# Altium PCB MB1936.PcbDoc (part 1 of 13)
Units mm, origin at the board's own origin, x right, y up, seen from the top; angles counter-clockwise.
Board outline 172 x 137 mm, 6 copper layers (Top Layer, Signal Layer 1, Signal Layer 2, Signal Layer 3, Signal Layer 4, Bottom Layer), stack 1.549 mm thick; 859 components, 672 nets, 3477 pads, 2222 vias.
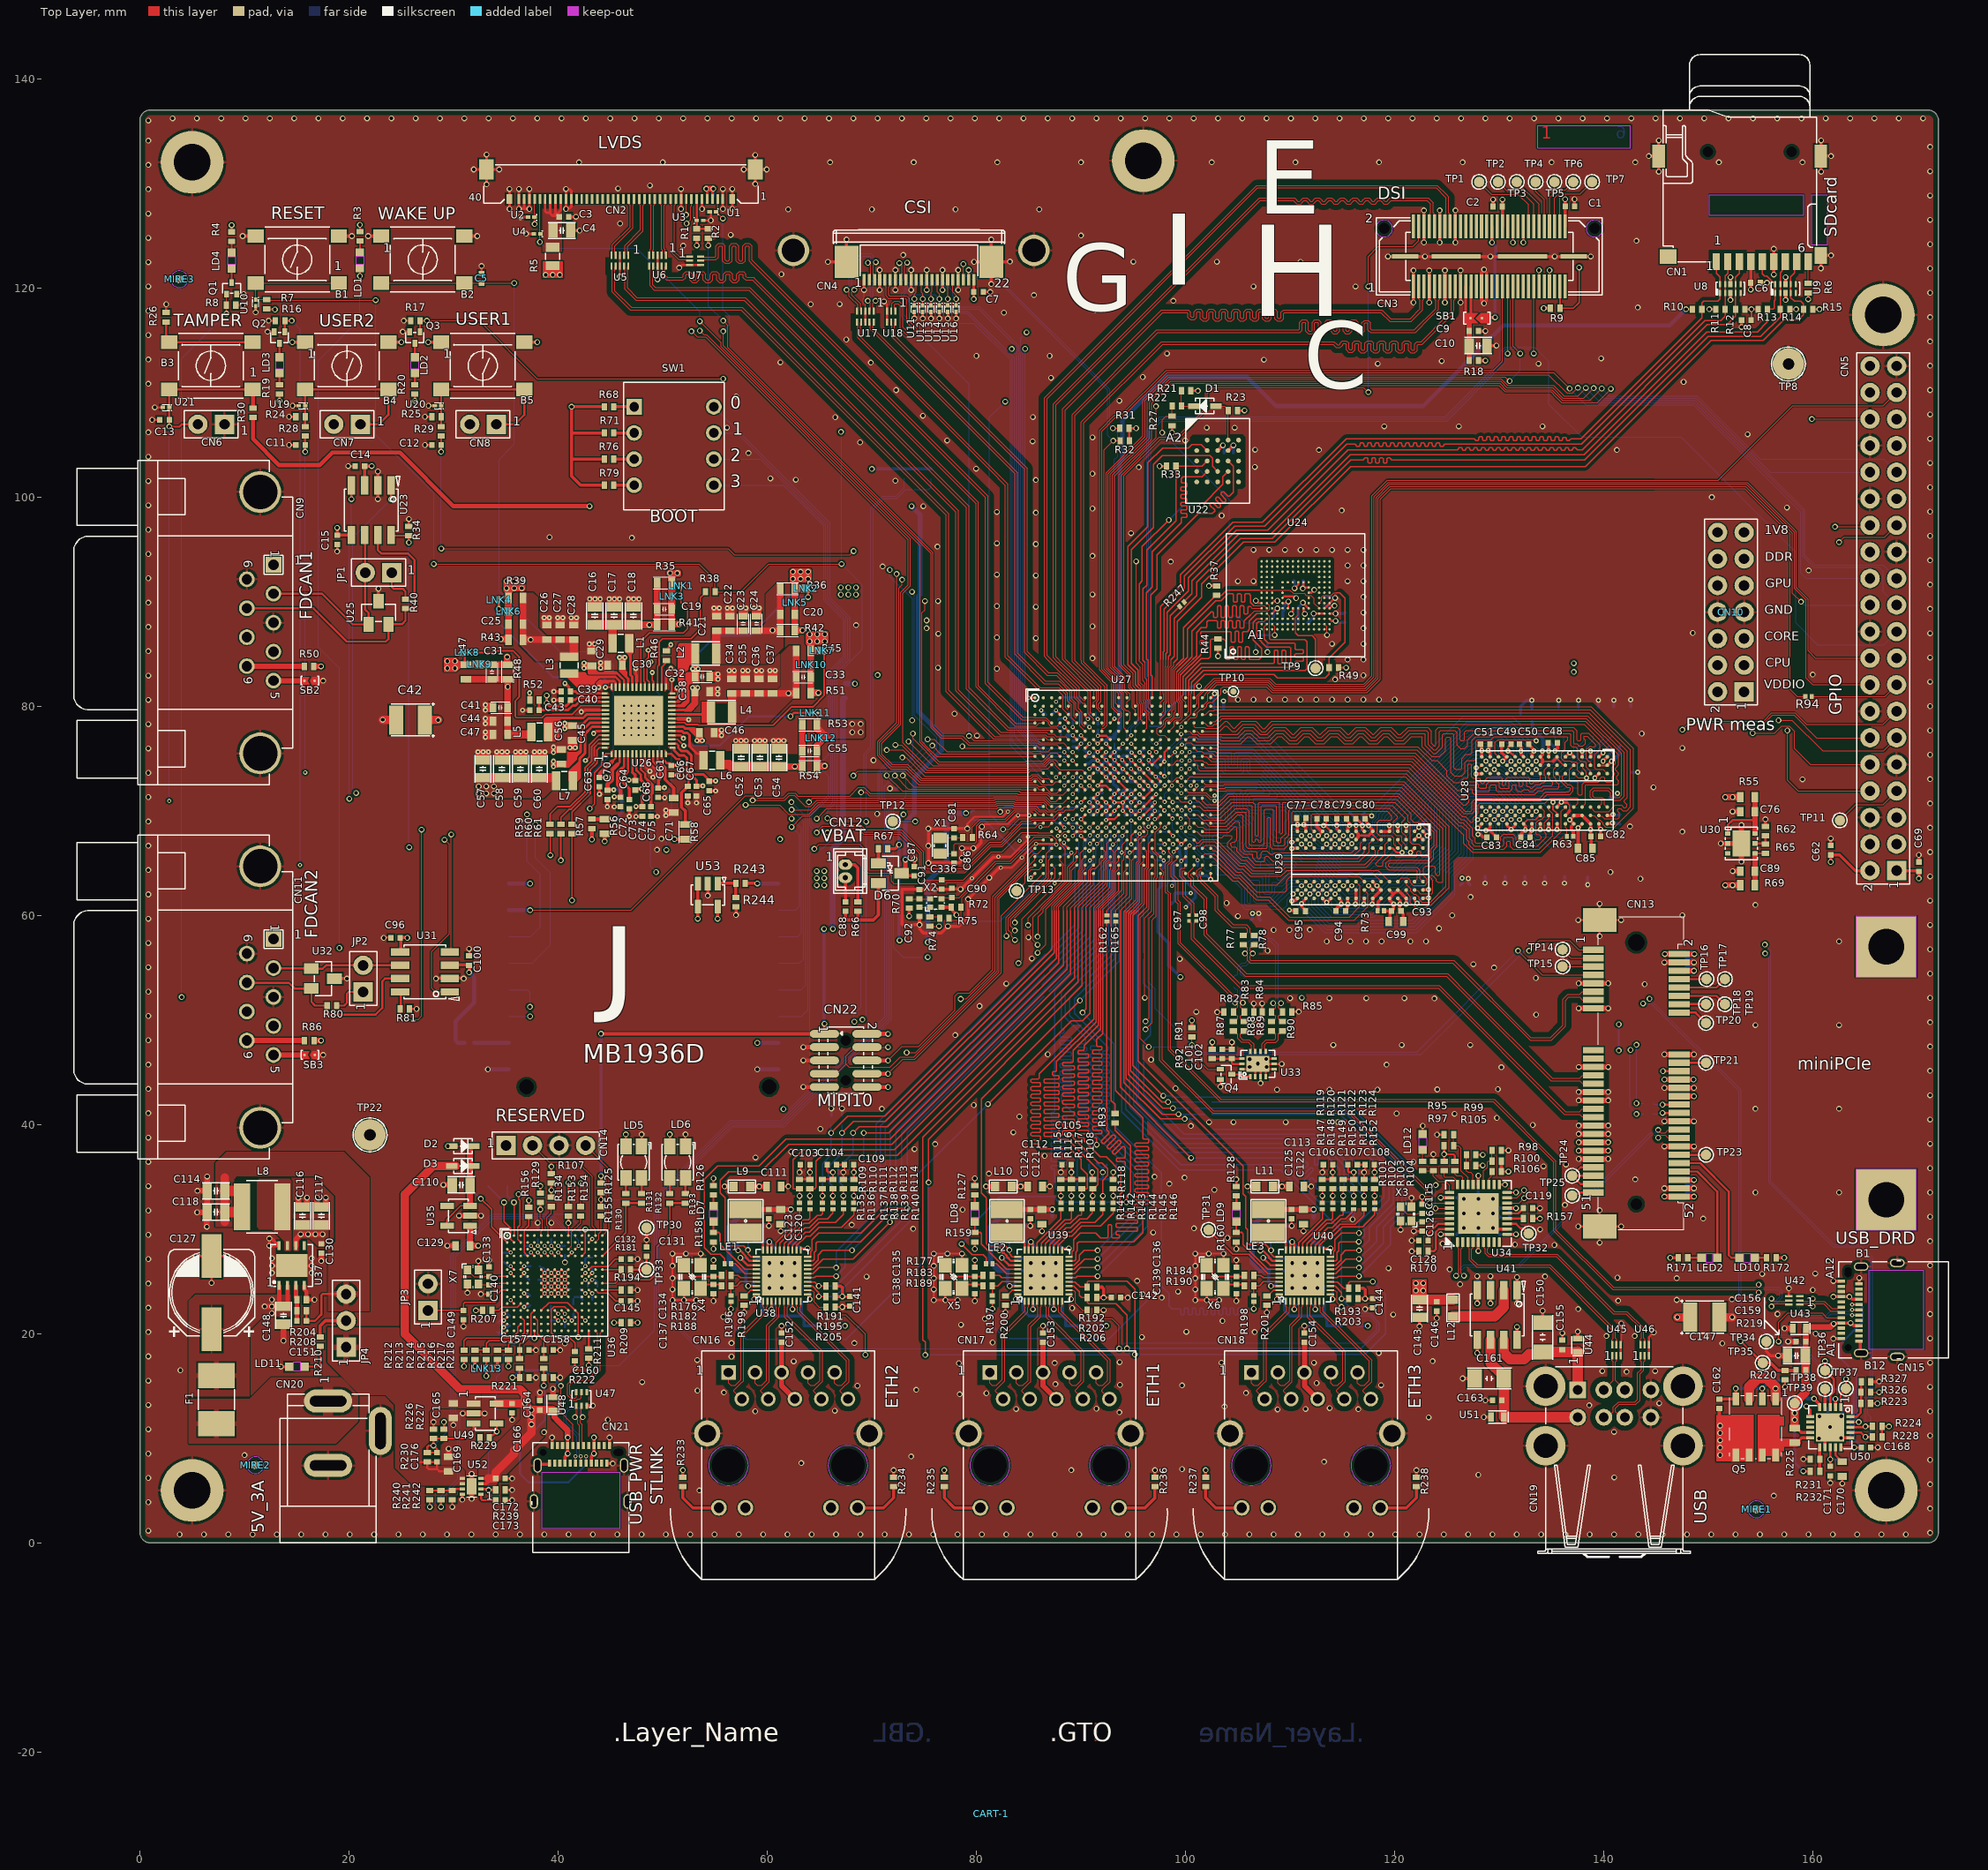
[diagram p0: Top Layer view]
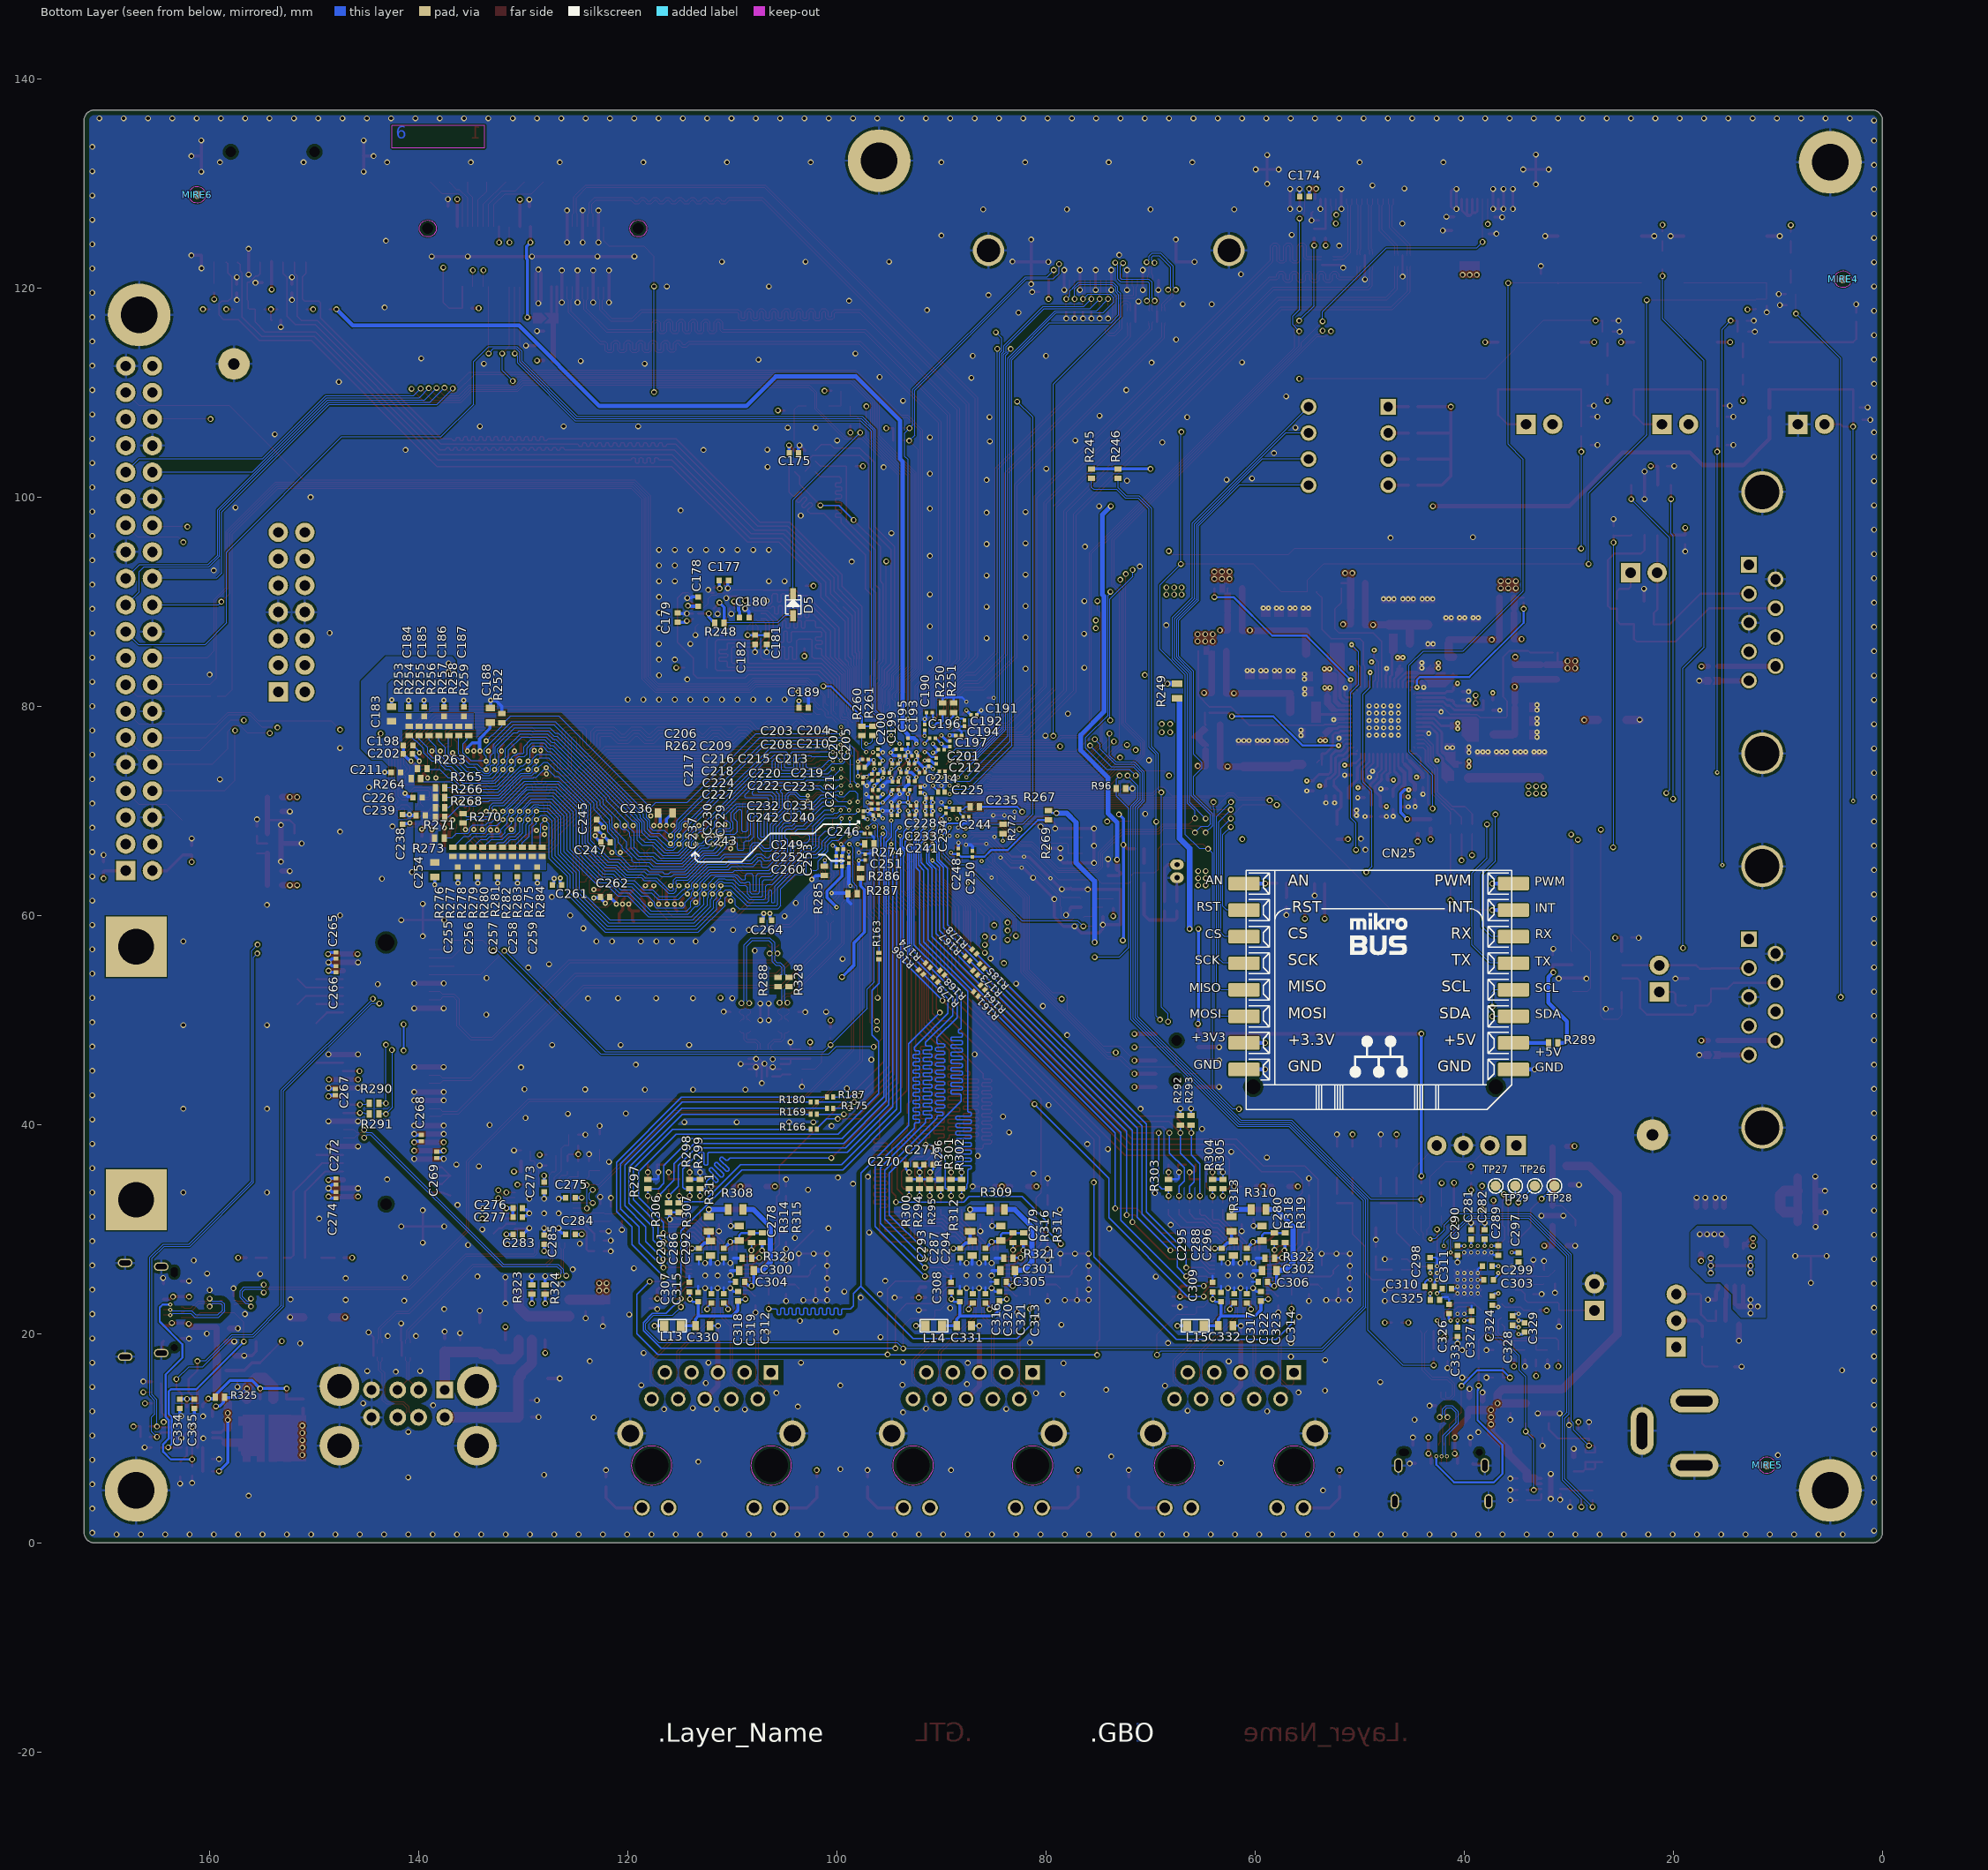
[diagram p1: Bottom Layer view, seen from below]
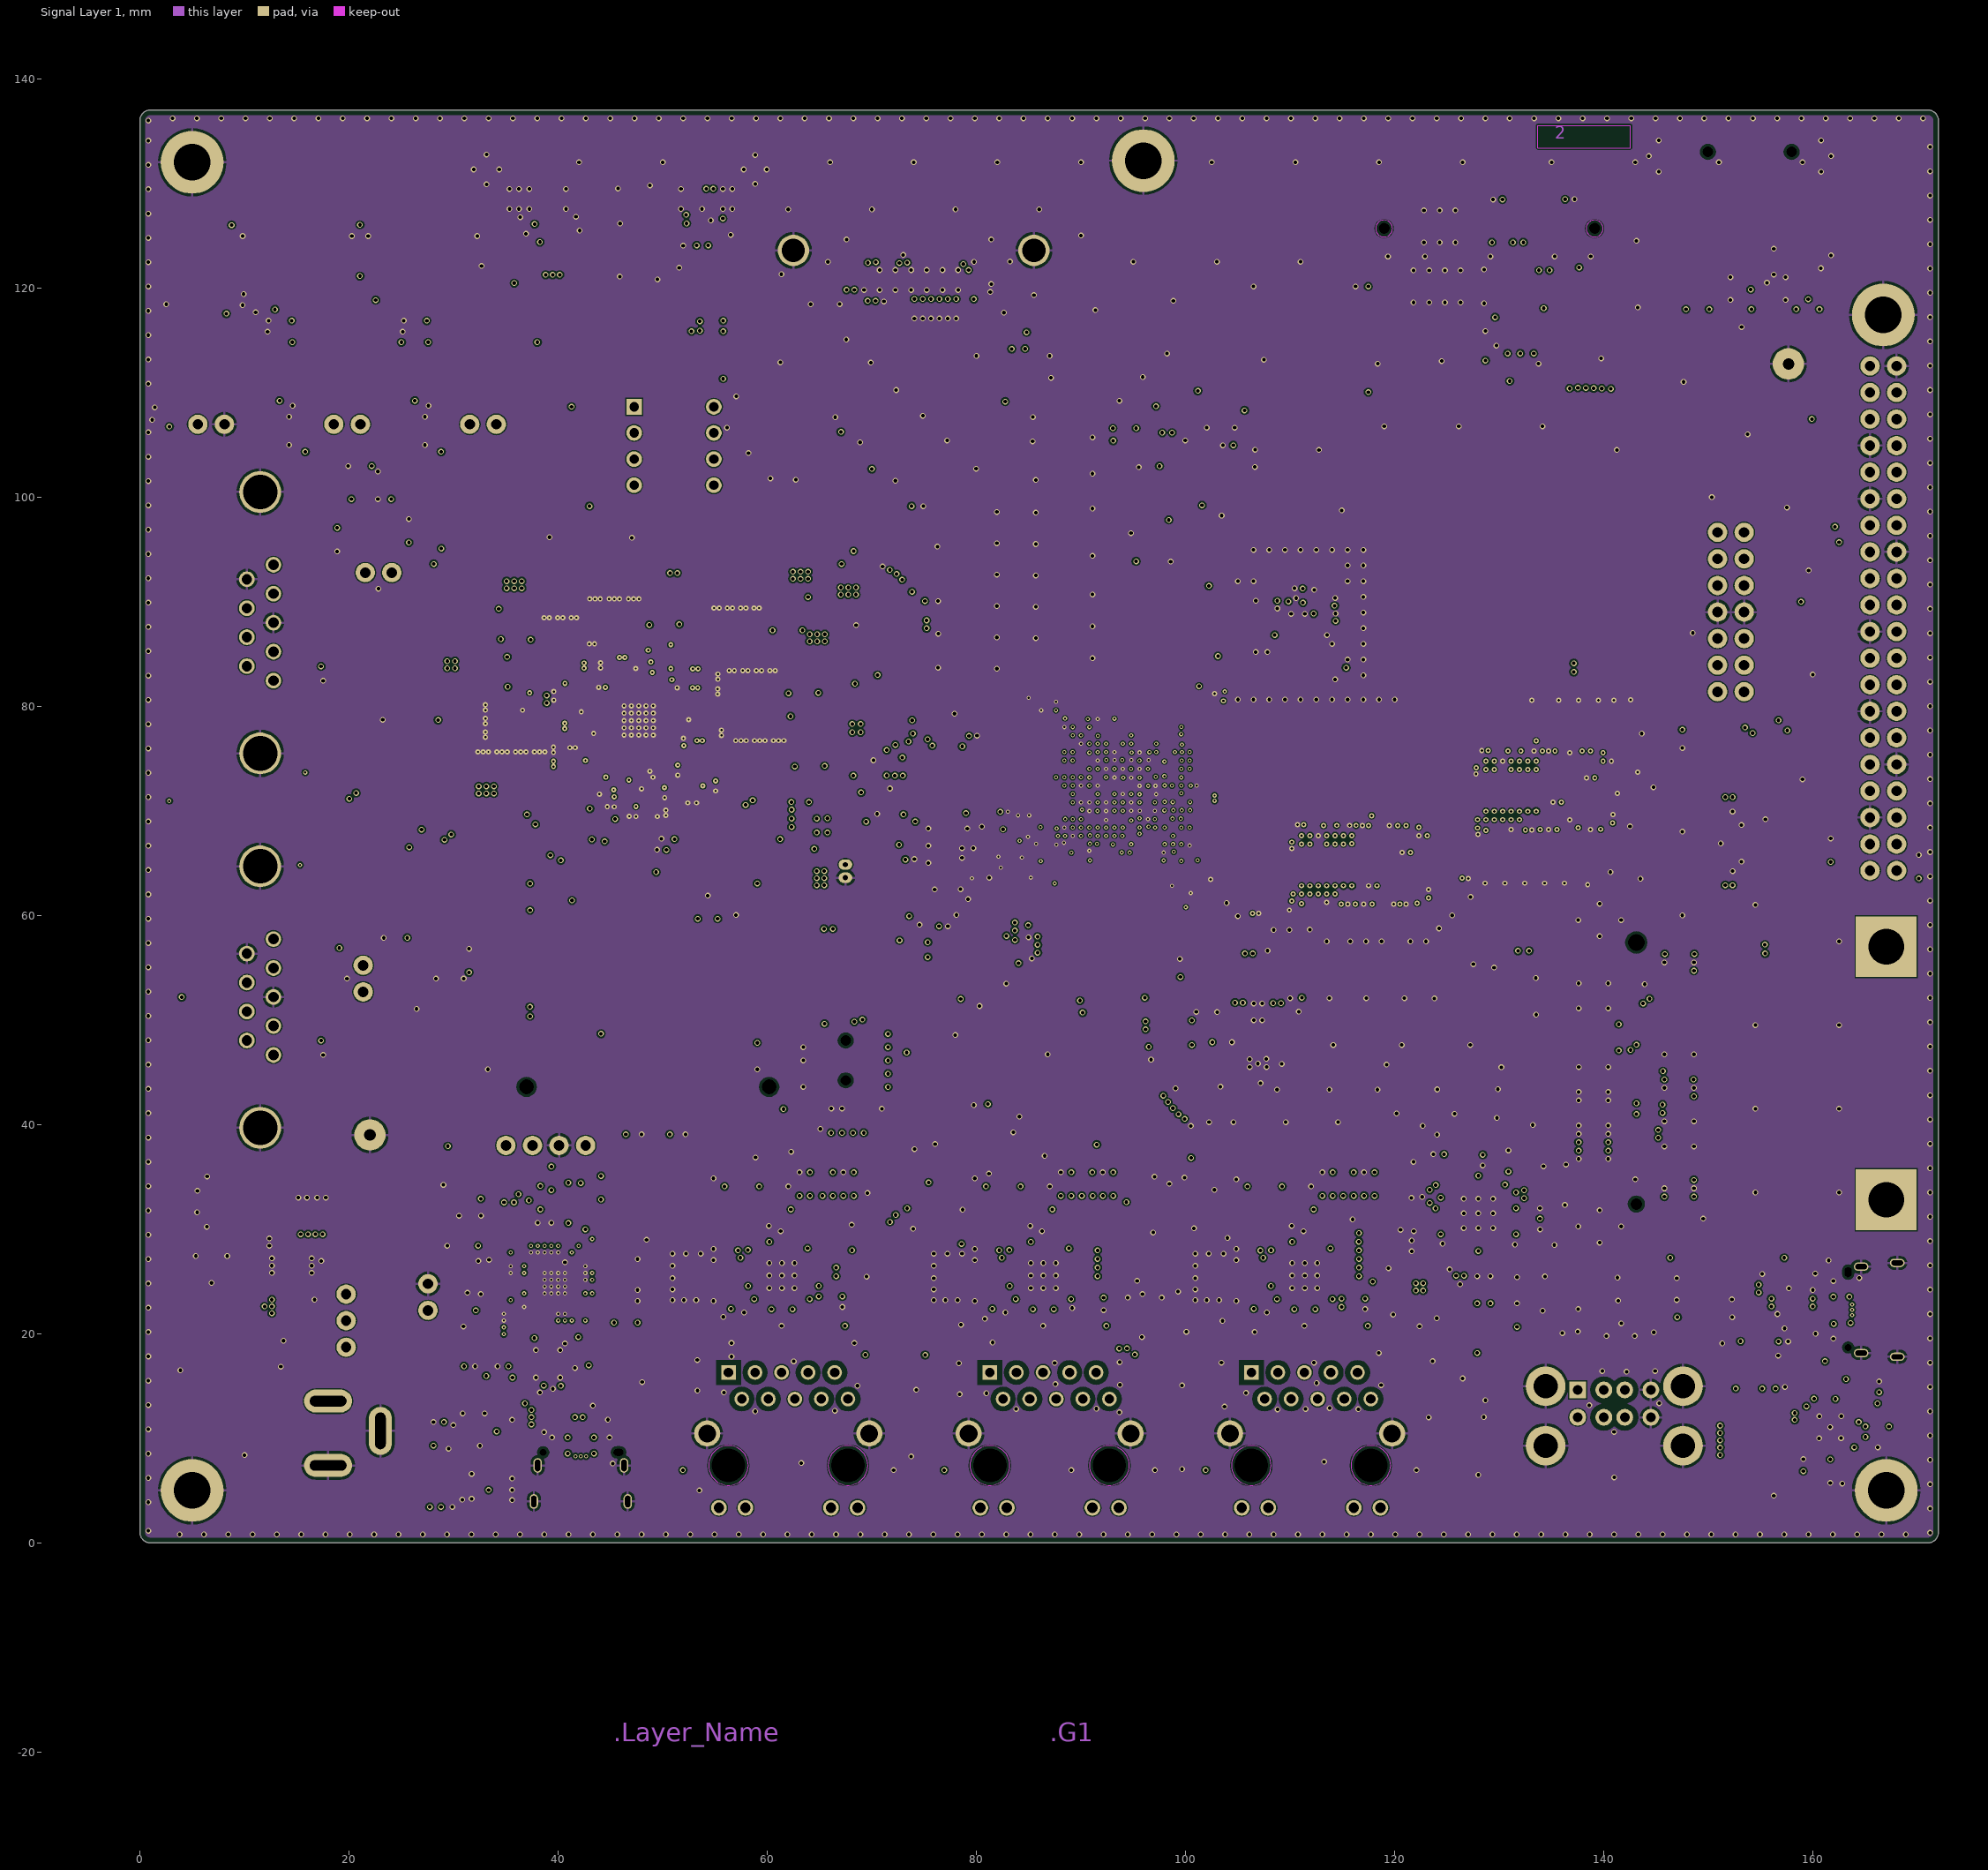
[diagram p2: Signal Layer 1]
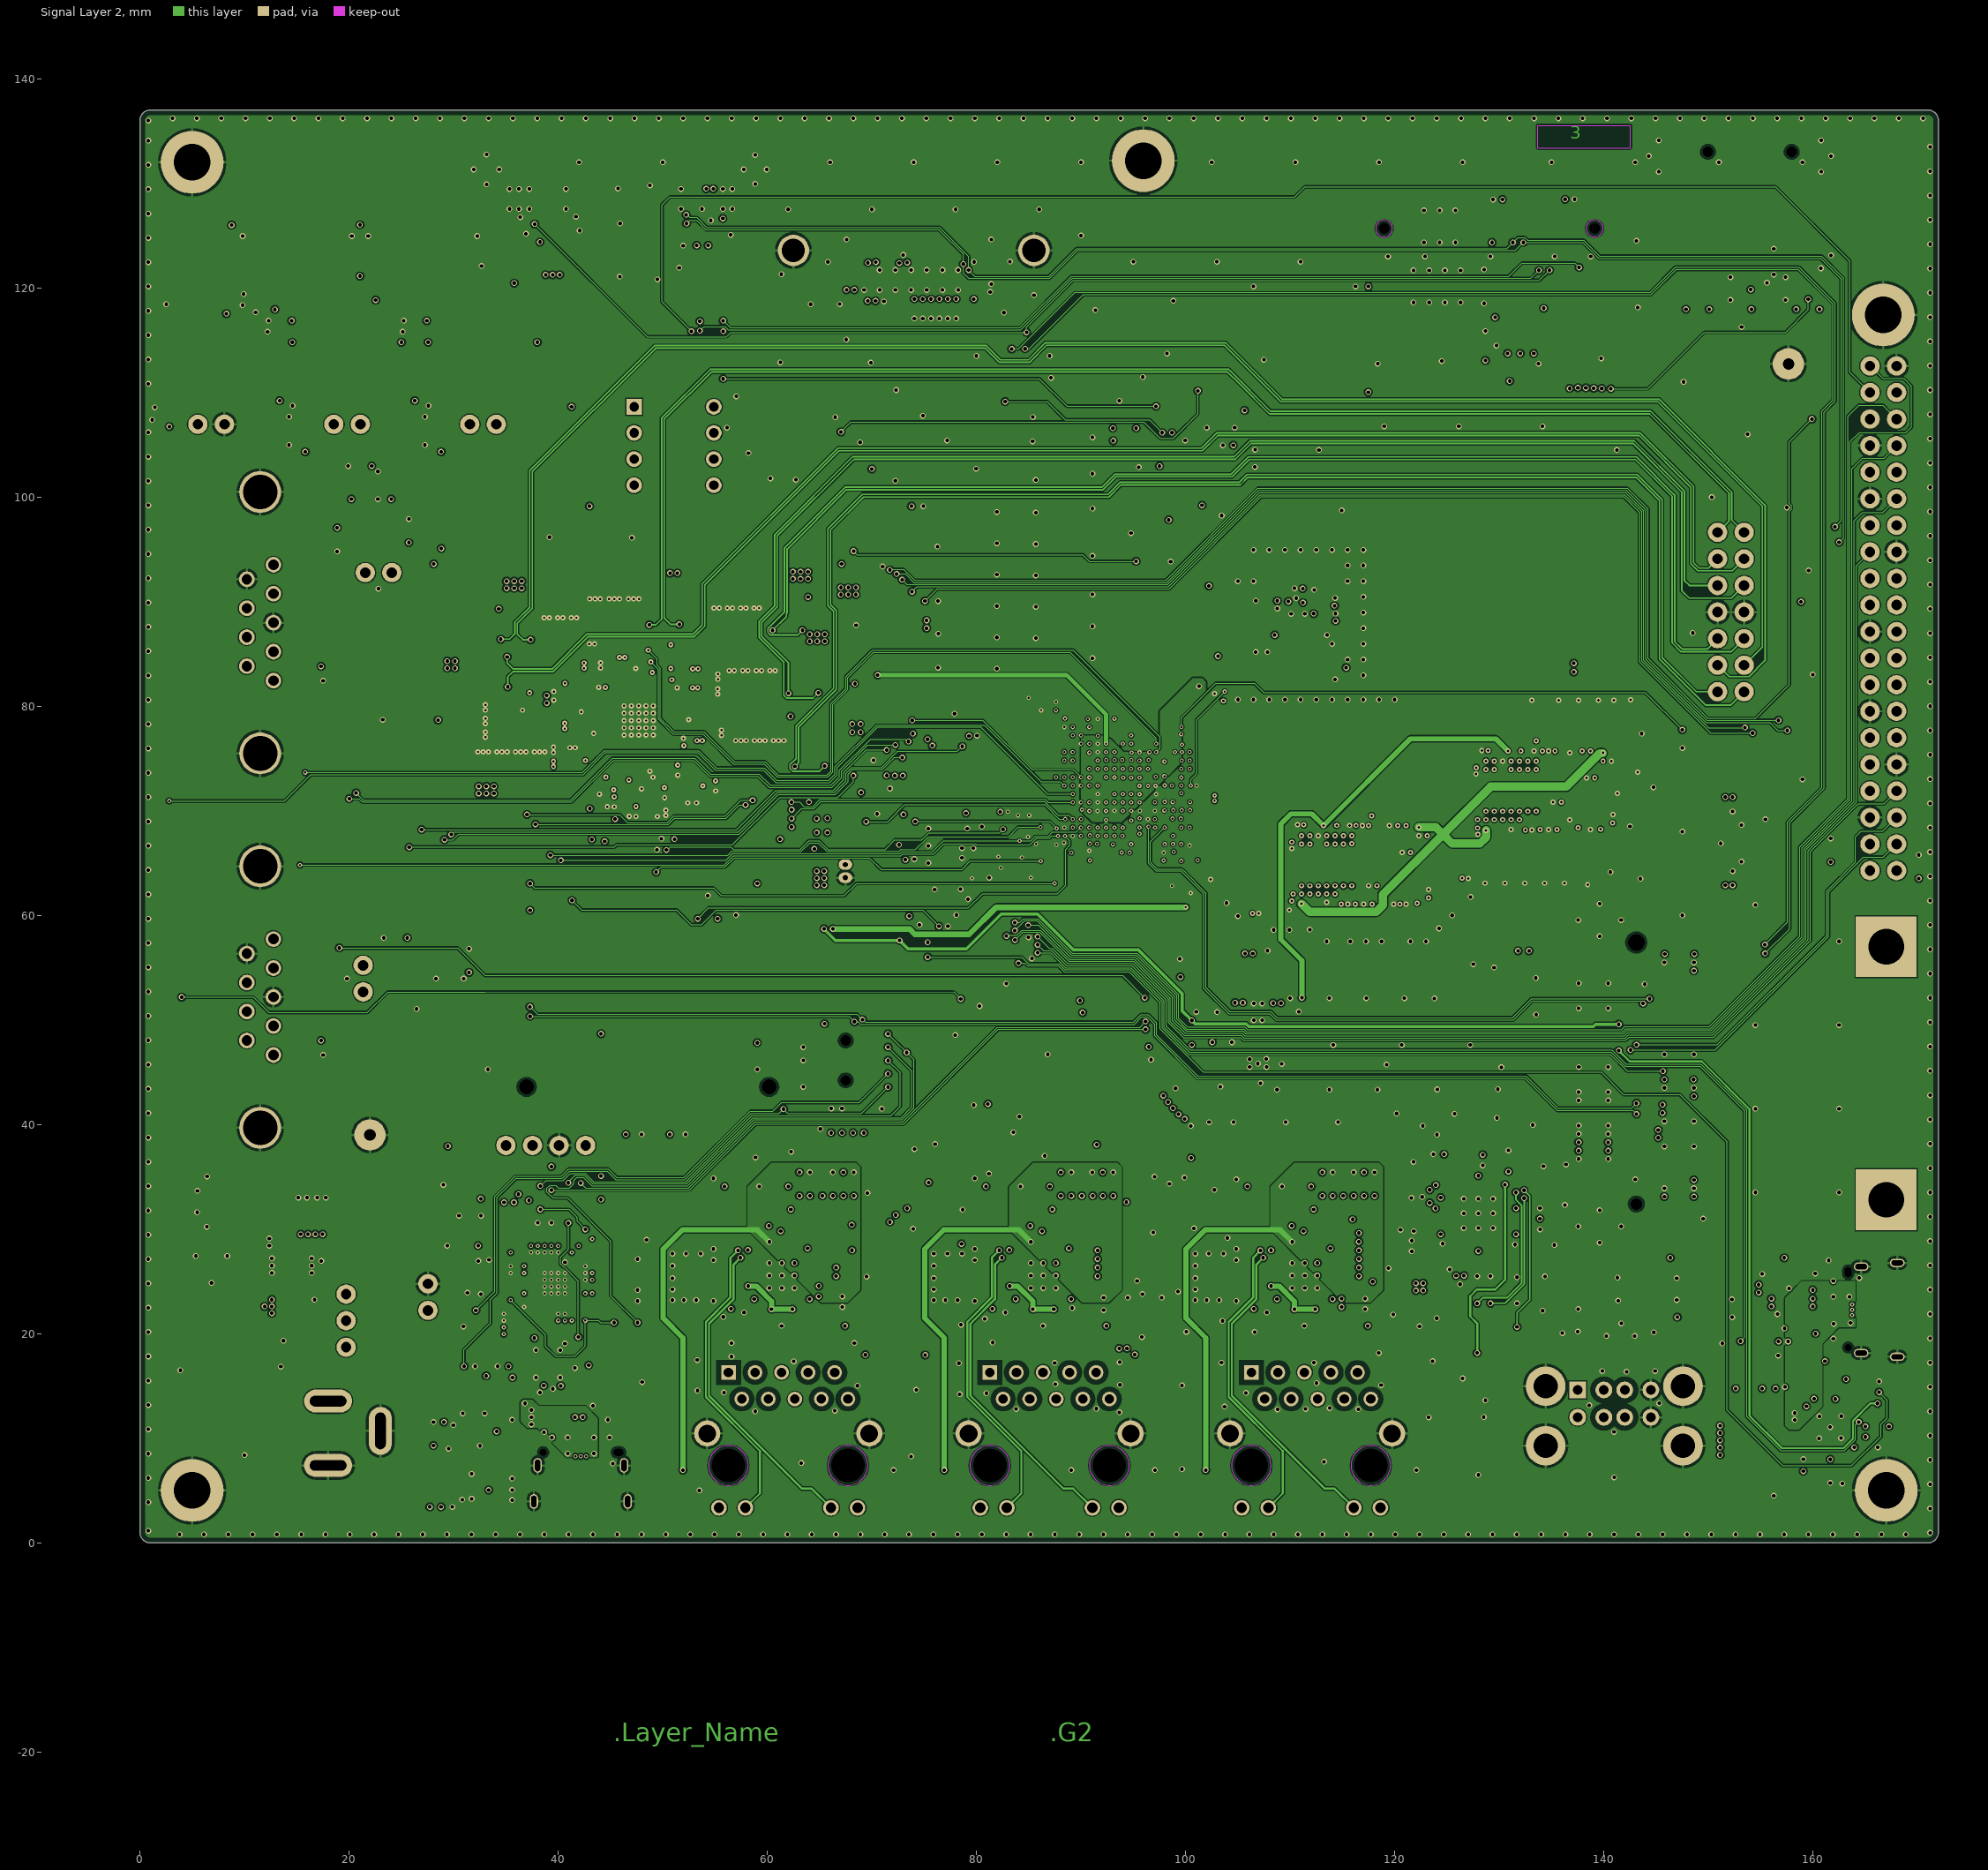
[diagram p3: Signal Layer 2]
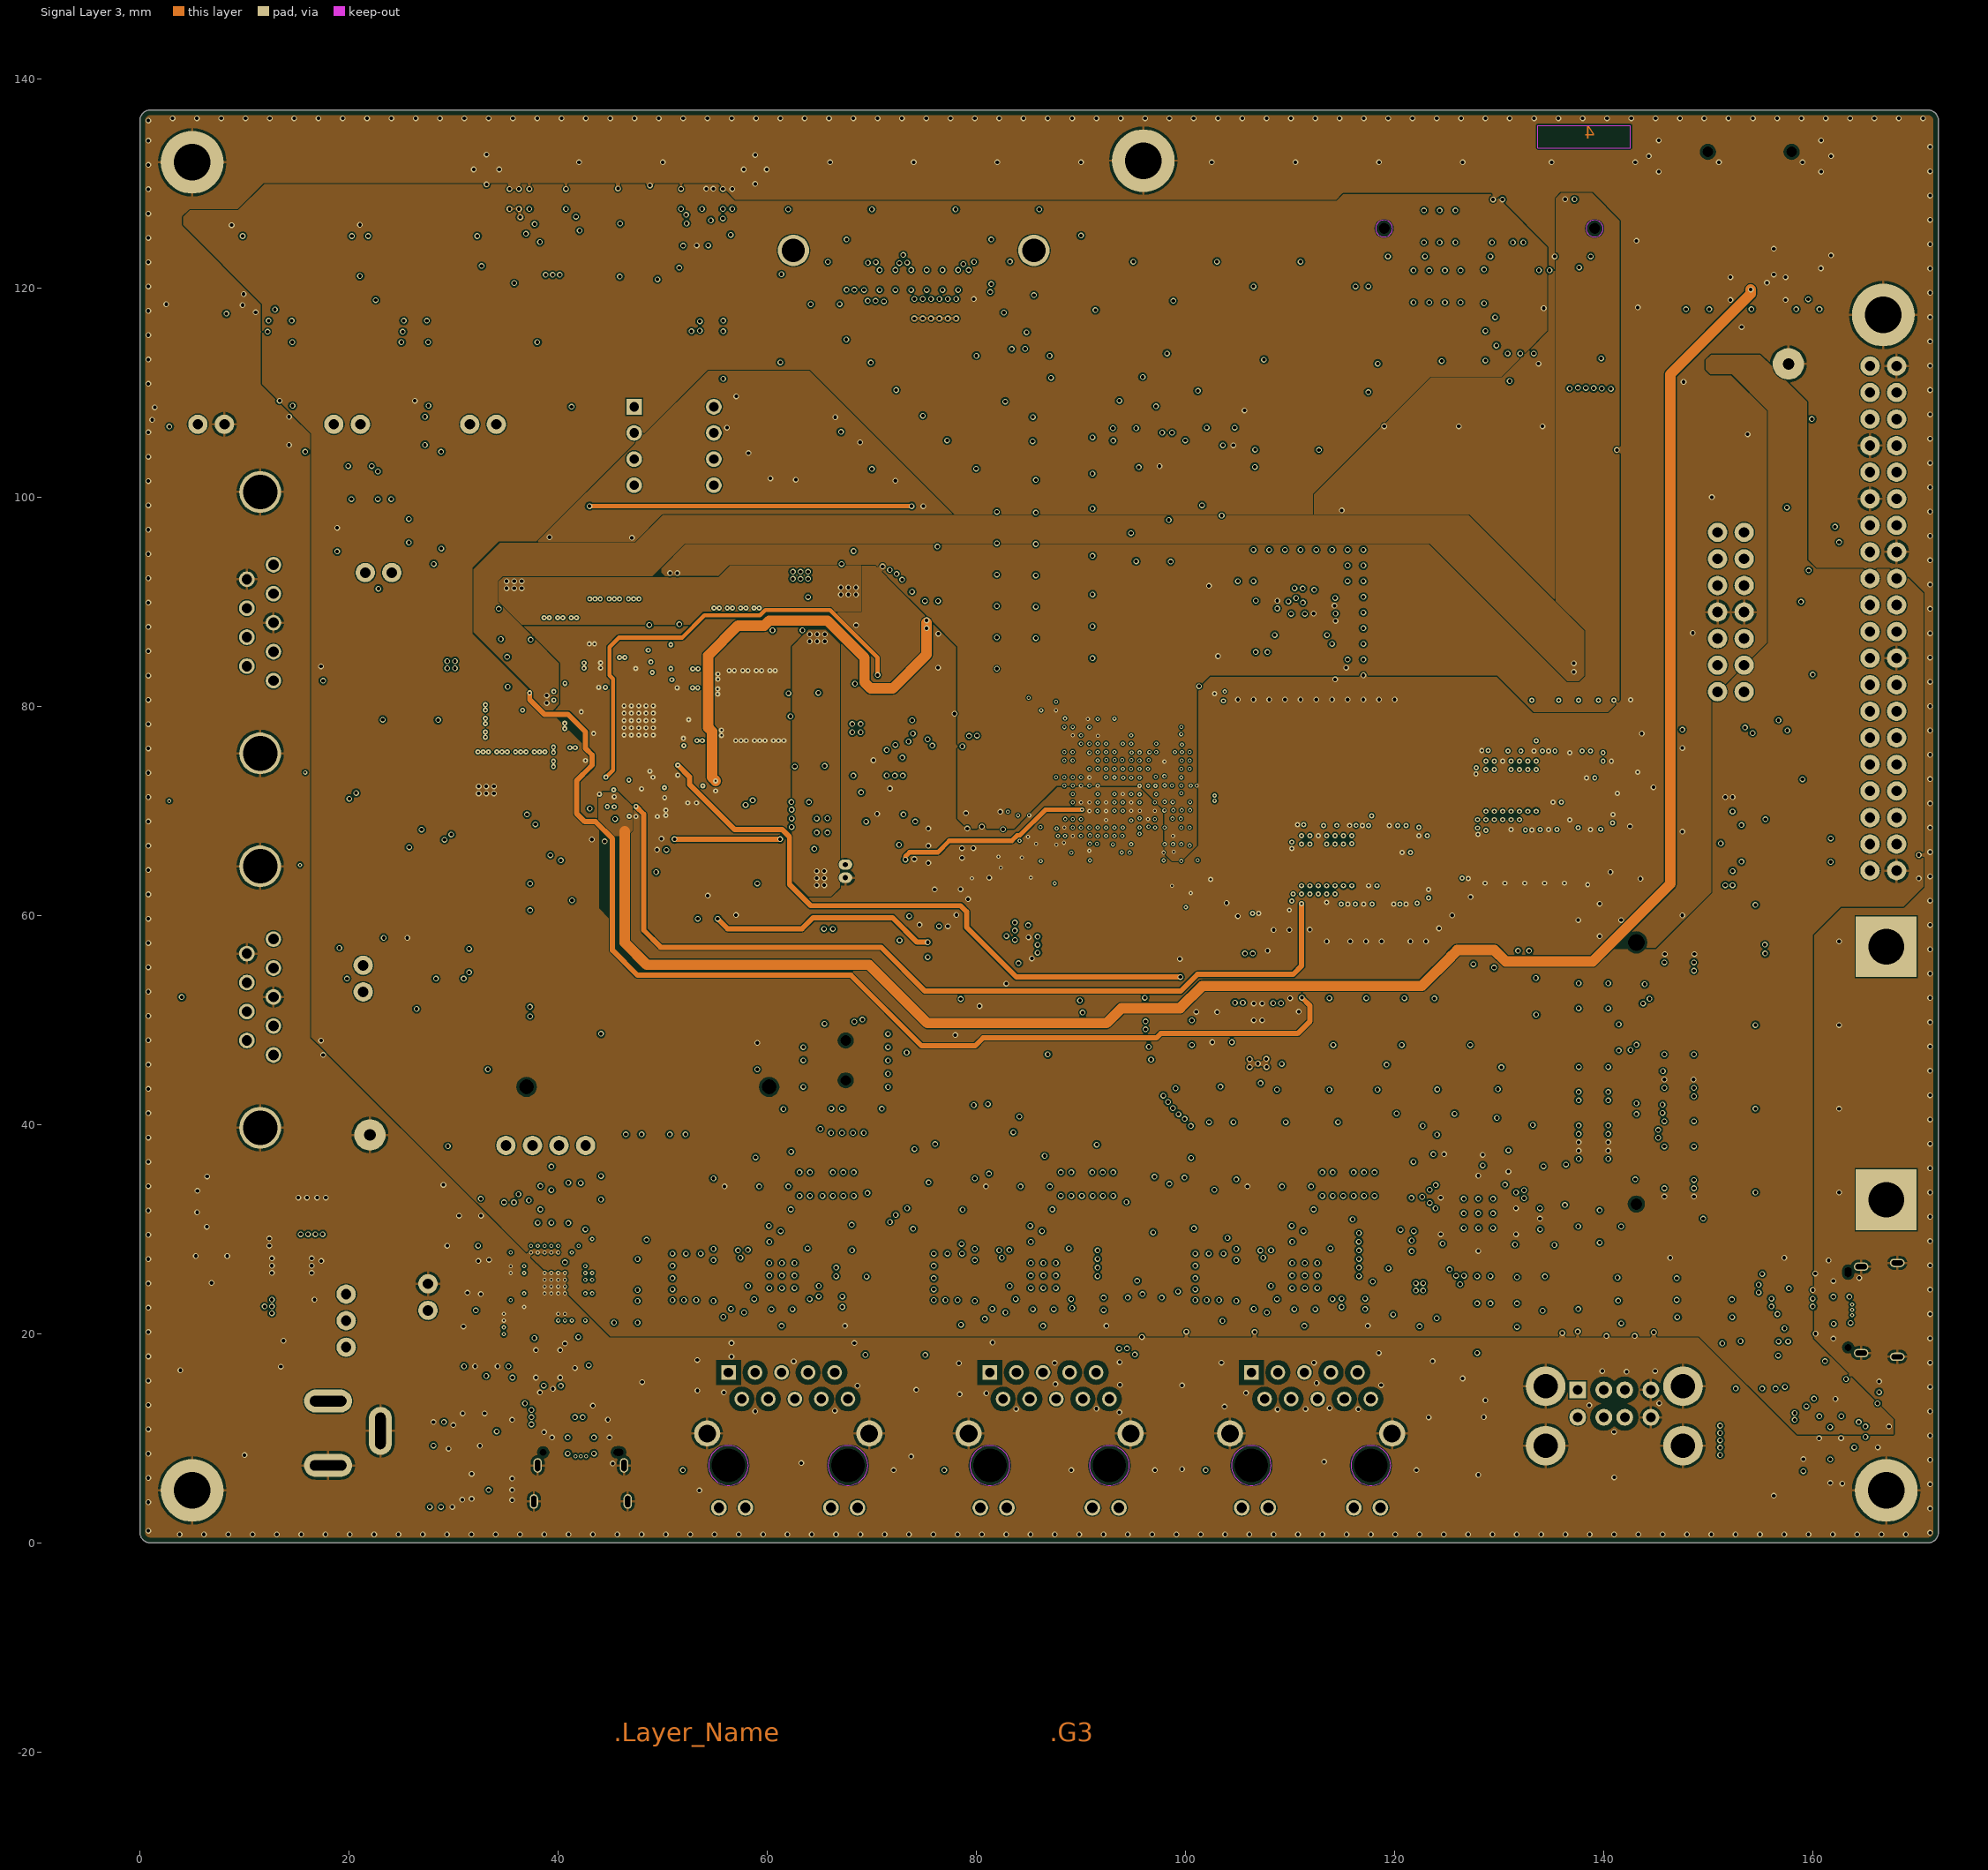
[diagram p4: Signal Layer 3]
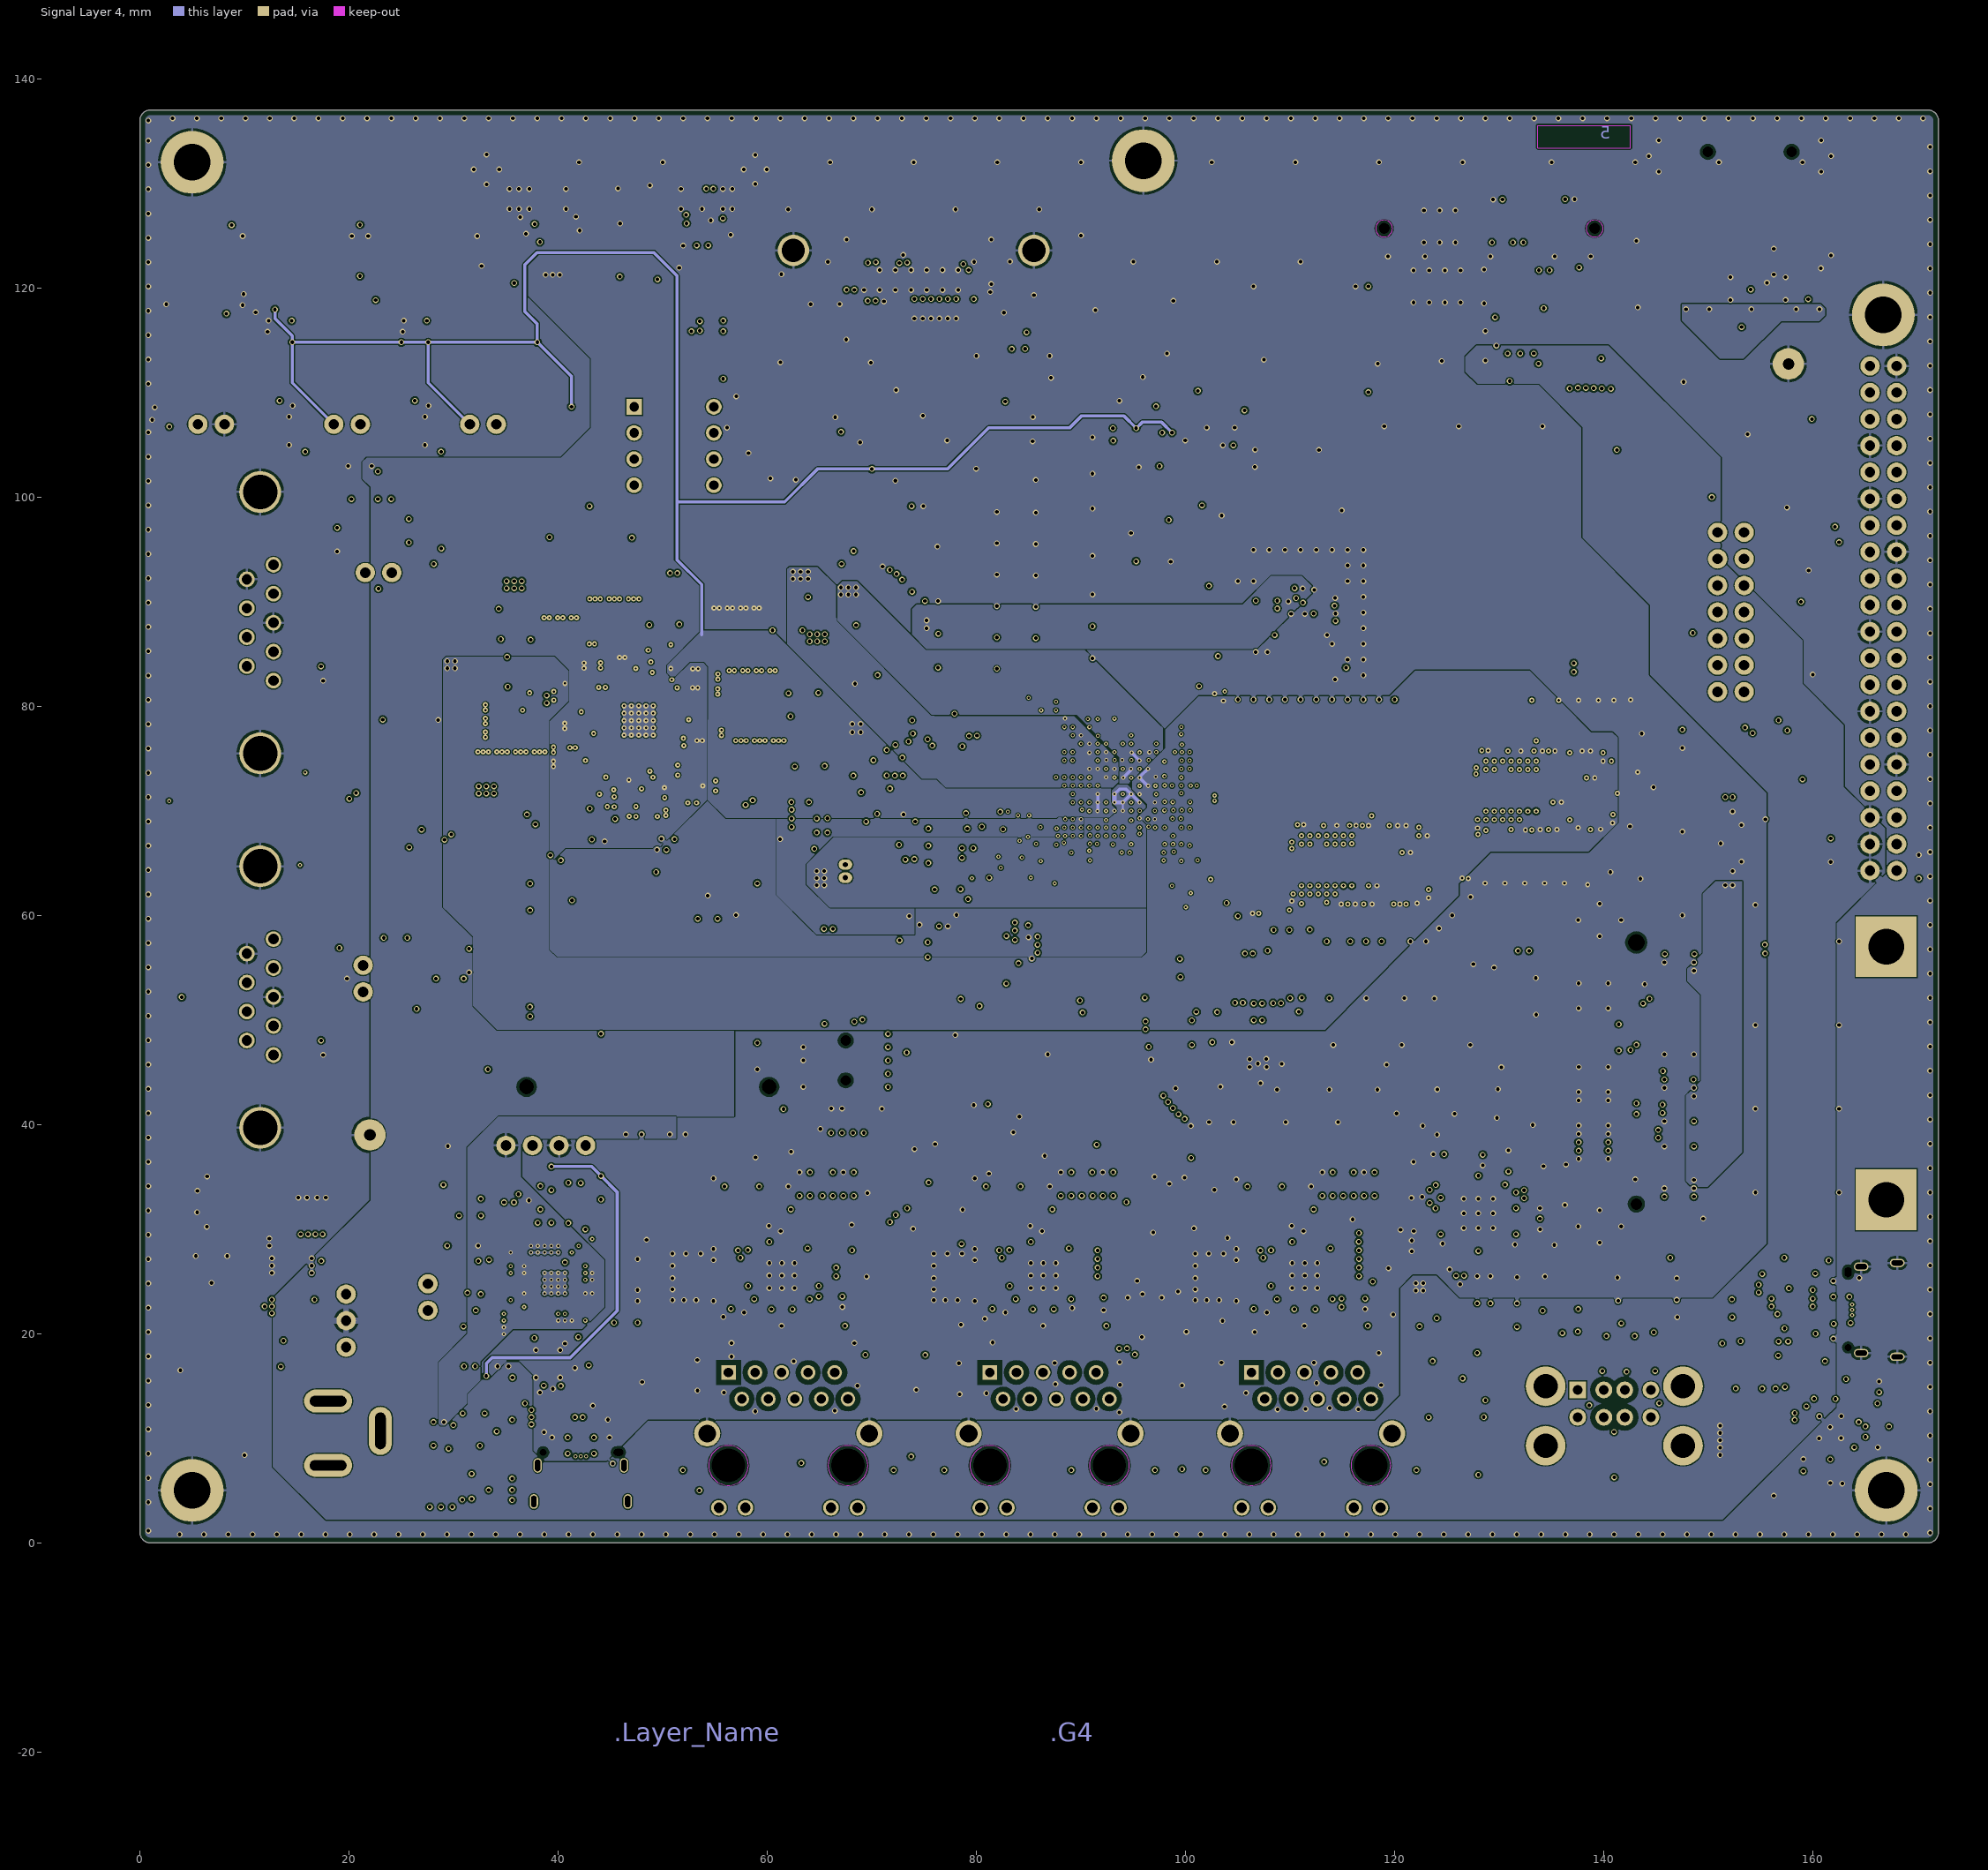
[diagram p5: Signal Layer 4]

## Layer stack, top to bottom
Top Solder: solder mask 0.025, Solder Resist, Dk 3.5
Top Layer: signal copper 0.037
Dielectric 1: prepreg 0.072, Dk 3.8
Signal Layer 1: signal copper 0.035
Dielectric 2: core 0.5, Dk 5
Signal Layer 2: signal copper 0.035
Dielectric 3: core 0.191, Dk 4.3
Signal Layer 3: signal copper 0.035
Dielectric 4: core 0.5, Dk 5
Signal Layer 4: signal copper 0.035
Dielectric 5: prepreg 0.072, Dk 3.8
Bottom Layer: signal copper 0.037
Bottom Solder: solder mask 0.025, Solder Resist, Dk 3.5

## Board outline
0,1 0,95 0,136 cw(c1,136) 1,137 171,137 cw(c171,136) 172,136 172,1 cw(c171,1) 171,0 1,0 cw(c1,1)

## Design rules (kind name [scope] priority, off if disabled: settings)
BoardOutlineClearance Silkscreen [OnLayer('Top Overlay') or OnLayer('Bottom Overlay')] p1: gap=0 ignorepadtopadclearanceinfootprint=FALSE
BoardOutlineClearance [All] p2: gap=0.5 ignorepadtopadclearanceinfootprint=FALSE
Clearance via_in_pad_ok [IsVia vs IsPad and ( (Name='U22-37') or (Name='U27-15') or (Name='U3-21') or (Name='U12-41') or (Name='U11-41') or (Name='U16-41') )] p1: gap=0.3 ignorepadtopadclearanceinfootprint=TRUE except(0: Track-Track Track-SMDPad Track-Via Track-Region SMDPad-Via SMDPad-Hole Via-Region Via-Hole; 0.1: Arc-Arc Arc-Track Arc-SMDPad Arc-THPad Arc-Via Arc-Poly Track-THPad Track-Poly SMDPad-THPad Via-Via Via-Poly Poly-Poly; 0.15: Track-Hole SMDPad-Poly SMDPad-Region Fill-Fill; 0.17: Region-Region; 0.19: Arc-Hole; 0.2: SMDPad-SMDPad THPad-THPad THPad-Via THPad-Poly; 0.25: THPad-Hole Fill-Hole Poly-Hole Region-Hole Text-Hole)
Clearance Clearance_POLY_DIFF-PAIRS [InDifferentialPairClass('DPC_ETH_100R') or InDifferentialPairClass('DPC_CSI_100R') or InDifferentialPairClass('DPC_DSI_100R') or  InDifferentialPairClass('DPC_USB_90R') or InDifferentialPairClass('DPC_DDR_100R') or InDifferentialPairClass('DPC_LVDS_100R') or InDifferentialPairClass('DPC_PCIE_100R') vs IsCopperRegion] p2: gap=0.3 ignorepadtopadclearanceinfootprint=TRUE except(0.1: Arc-Arc Arc-Track Arc-Via Track-Track Track-SMDPad Track-Via Via-Via; 0.12: SMDPad-Via; 0.15: Arc-SMDPad Arc-THPad Track-THPad Track-Region SMDPad-Region Via-Poly; 0.17: Region-Region; 0.2: Track-Hole SMDPad-SMDPad SMDPad-THPad THPad-THPad THPad-Via Via-Hole; 0.245: SMDPad-Hole; 0.25: Arc-Hole THPad-Hole Fill-Hole Poly-Hole Region-Hole Text-Hole; 0.48: Arc-Poly Track-Poly SMDPad-Poly THPad-Poly Fill-Poly Poly-Poly)
Clearance Clearance_BGA-STLINK [HasFootprint('ICC_UFBGA201_176+25_10X10_P065')] p3: gap=0.3 ignorepadtopadclearanceinfootprint=TRUE except(0.1: Arc-Arc Arc-Track Arc-SMDPad Arc-THPad Arc-Via Arc-Poly Track-Track Track-SMDPad Track-THPad Track-Via Track-Poly SMDPad-THPad Via-Via Via-Poly; 0.12: SMDPad-Via; 0.15: Track-Region SMDPad-Poly SMDPad-Region Poly-Poly; 0.17: Region-Region; 0.2: Track-Hole SMDPad-SMDPad THPad-THPad THPad-Via THPad-Poly Via-Hole; 0.23: SMDPad-Hole; 0.25: Arc-Hole THPad-Hole Fill-Hole Poly-Hole Region-Hole Text-Hole)
Clearance Clearance_BGA-MCU [WithinRoom('RoomDefinition_MCU')] p4: gap=0.3 ignorepadtopadclearanceinfootprint=TRUE except(0.09: Arc-Arc Arc-Track Track-Track Track-SMDPad; 0.1: Arc-SMDPad Arc-THPad Arc-Via Arc-Poly Track-THPad Track-Via Track-Poly SMDPad-THPad SMDPad-Via Via-Via Via-Poly; 0.15: Track-Region SMDPad-Poly SMDPad-Region Poly-Poly; 0.17: Region-Region; 0.2: Track-Hole SMDPad-SMDPad SMDPad-Hole THPad-THPad THPad-Via THPad-Poly Via-Hole Poly-Hole; 0.25: Arc-Hole THPad-Hole Fill-Hole Region-Hole Text-Hole)
Clearance Clearance_BGA-DDR [isvia and WithinRoom('RoomDefinition_DDR') vs IsVia or IsCopperRegion] p5: gap=0.3 ignorepadtopadclearanceinfootprint=TRUE except(0.09: Arc-Arc Arc-Track; 0.1: Arc-SMDPad Arc-THPad Arc-Via Arc-Poly Track-SMDPad Track-THPad Track-Via Track-Poly SMDPad-THPad SMDPad-Via Via-Via Via-Poly; 0.15: Track-Region SMDPad-Poly SMDPad-Region Poly-Poly; 0.17: Region-Region; 0.2: Track-Track Track-Hole SMDPad-SMDPad SMDPad-Hole THPad-THPad THPad-Via THPad-Poly Via-Hole Poly-Hole; 0.25: Arc-Hole THPad-Hole Fill-Hole Region-Hole Text-Hole)
Clearance Clearance_BGA-EMMC_U7 [WithinRoom('RoomDefinition_eMMC')] p6: gap=0.3 ignorepadtopadclearanceinfootprint=TRUE except(0.09: Arc-Arc Arc-Track Track-Track Track-SMDPad; 0.1: Arc-SMDPad Arc-THPad Arc-Via Arc-Poly Track-THPad Track-Via Track-Poly SMDPad-THPad SMDPad-Via Via-Via Via-Poly; 0.15: Track-Region SMDPad-Poly SMDPad-Region Poly-Poly; 0.17: Region-Region; 0.2: Track-Hole SMDPad-SMDPad SMDPad-Hole THPad-THPad THPad-Via THPad-Poly Via-Hole; 0.25: Arc-Hole THPad-Hole Fill-Hole Poly-Hole Region-Hole Text-Hole)
Clearance Clearance_SINGLE_55R [InNetClass('NC_SINGLE_DDR_55R') or InNetClass('NC_SINGLE_RGMII_ALL_50R_AND_CLK') or InNetClass('NC_SINGLE_SDMMC1_50R') or  InNetClass('NC_SINGLE_SDMMC2_50R') or  InNetClass('NC_SINGLE_QSPI_50R') or InNetClass('NC_SINGLE_OCTOSPI_50R') vs IsCopperRegion] p7: gap=0.3 ignorepadtopadclearanceinfootprint=TRUE except(0.1: Arc-Arc Arc-Track Arc-SMDPad Arc-THPad Arc-Via Track-SMDPad Track-THPad Track-Via Track-Region SMDPad-SMDPad SMDPad-THPad SMDPad-Via SMDPad-Region THPad-THPad THPad-Via Via-Via Region-Region; 0.15: Via-Poly; 0.2: Track-Track Track-Hole Via-Hole; 0.245: SMDPad-Hole; 0.25: Arc-Hole THPad-Hole Fill-Hole Poly-Hole Region-Hole Text-Hole; 0.33: Arc-Poly Track-Poly SMDPad-Poly THPad-Poly Fill-Poly Poly-Poly)
Clearance Clearance_Default_SAME-NETS [IsTrack vs IsPad] p8: gap=0.1 ignorepadtopadclearanceinfootprint=TRUE except(0: Track-Track Track-SMDPad Track-Via Track-Region SMDPad-Hole Via-Region Via-Hole; 0.05: SMDPad-Via; 0.15: Track-Hole; 0.19: Arc-Hole; 0.25: THPad-Hole Fill-Hole Poly-Hole Region-Hole Text-Hole)
Clearance Clearance_Default [All] p9: gap=0.1 ignorepadtopadclearanceinfootprint=TRUE except(0.2: Track-Hole; 0.245: SMDPad-Hole; 0.25: Arc-Hole THPad-Hole Via-Hole Fill-Hole Poly-Hole Region-Hole Text-Hole)
ComponentClearance [All] p1: gap=0.2 collisioncheckmode=3 verticalgap=0 showdistances=FALSE
DiffPairsRouting DiffPairsRouting_DSI_100R [InDifferentialPairClass('DPC_DSI_100R')] p1: maxlimit=0.16 minlimit=0.1 mostfreqgap=0.254 toplayer_prefgap=0.16 toplayer_minwidth=0.09 toplayer_maxwidth=0.09 toplayer_prefwidth=0.09 bottomlayer_mingap=0.16 bottomlayer_prefgap=0.16 bottomlayer_minwidth=0.09 bottomlayer_maxwidth=0.09 bottomlayer_prefwidth=0.09 impedanceprofiledriven=TRUE impedanceprofileid={5106416E-43F8-41F8-8BCA-F68B3FB1C141} impedanceprofilevalue=100.000000 maxuncoupledlength=12.7
DiffPairsRouting DiffPairsRouting_DDR_100R [InDifferentialPairClass('DPC_DDR_100R')] p2: maxlimit=0.16 minlimit=0.14 mostfreqgap=0.254 toplayer_mingap=0.16 toplayer_prefgap=0.16 toplayer_minwidth=0.09 toplayer_maxwidth=0.09 toplayer_prefwidth=0.09 bottomlayer_mingap=0.16 bottomlayer_prefgap=0.16 bottomlayer_minwidth=0.09 bottomlayer_maxwidth=0.09 bottomlayer_prefwidth=0.09 impedanceprofiledriven=TRUE impedanceprofileid={5106416E-43F8-41F8-8BCA-F68B3FB1C141} impedanceprofilevalue=100.000000 maxuncoupledlength=12.7
DiffPairsRouting DiffPairsRouting_PCIE_100R [InDifferentialPairClass('DPC_PCIE_100R')] p3: maxlimit=0.16 minlimit=0.14 mostfreqgap=0.254 toplayer_prefgap=0.16 toplayer_minwidth=0.09 toplayer_maxwidth=0.09 toplayer_prefwidth=0.09 bottomlayer_mingap=0.16 bottomlayer_prefgap=0.16 bottomlayer_minwidth=0.09 bottomlayer_maxwidth=0.09 bottomlayer_prefwidth=0.09 impedanceprofiledriven=TRUE impedanceprofileid={5106416E-43F8-41F8-8BCA-F68B3FB1C141} impedanceprofilevalue=100.000000 maxuncoupledlength=12.7
DiffPairsRouting DiffPairsRouting_LVDS_100R [InDifferentialPairClass('DPC_LVDS_100R')] p4: maxlimit=0.16 minlimit=0.1 mostfreqgap=0.254 toplayer_prefgap=0.16 toplayer_minwidth=0.09 toplayer_maxwidth=0.09 toplayer_prefwidth=0.09 bottomlayer_mingap=0.16 bottomlayer_prefgap=0.16 bottomlayer_minwidth=0.09 bottomlayer_maxwidth=0.09 bottomlayer_prefwidth=0.09 impedanceprofiledriven=TRUE impedanceprofileid={5106416E-43F8-41F8-8BCA-F68B3FB1C141} impedanceprofilevalue=100.000000 maxuncoupledlength=12.7
DiffPairsRouting DiffPairsRouting_LVDS_100R_CON [InDifferentialPairClass('DPC_LVDS_100R_CON')] p5: maxlimit=0.16 minlimit=0.1 mostfreqgap=0.254 toplayer_prefgap=0.16 toplayer_minwidth=0.09 toplayer_maxwidth=0.09 toplayer_prefwidth=0.09 bottomlayer_mingap=0.16 bottomlayer_prefgap=0.16 bottomlayer_minwidth=0.09 bottomlayer_maxwidth=0.09 bottomlayer_prefwidth=0.09 impedanceprofiledriven=TRUE impedanceprofileid={5106416E-43F8-41F8-8BCA-F68B3FB1C141} impedanceprofilevalue=100.000000 maxuncoupledlength=12.7
DiffPairsRouting DiffPairsRouting_CSI_100R [InDifferentialPairClass('DPC_CSI_100R')] p6: maxlimit=0.16 minlimit=0.1 mostfreqgap=0.254 toplayer_prefgap=0.16 toplayer_minwidth=0.09 toplayer_maxwidth=0.09 toplayer_prefwidth=0.09 bottomlayer_mingap=0.16 bottomlayer_prefgap=0.16 bottomlayer_minwidth=0.09 bottomlayer_maxwidth=0.09 bottomlayer_prefwidth=0.09 impedanceprofiledriven=TRUE impedanceprofileid={5106416E-43F8-41F8-8BCA-F68B3FB1C141} impedanceprofilevalue=100.000000 maxuncoupledlength=12.7
DiffPairsRouting DiffPairsRouting_CSI_100R_CON [InDifferentialPairClass('DPC_CSI_100R_CON')] p7: maxlimit=0.16 minlimit=0.1 mostfreqgap=0.254 toplayer_prefgap=0.16 toplayer_minwidth=0.09 toplayer_maxwidth=0.09 toplayer_prefwidth=0.09 bottomlayer_mingap=0.16 bottomlayer_prefgap=0.16 bottomlayer_minwidth=0.09 bottomlayer_maxwidth=0.09 bottomlayer_prefwidth=0.09 impedanceprofiledriven=TRUE impedanceprofileid={5106416E-43F8-41F8-8BCA-F68B3FB1C141} impedanceprofilevalue=100.000000 maxuncoupledlength=12.7
DiffPairsRouting DiffPairsRouting_USB_90R [InDifferentialPairClass('DPC_USB_90R')] p8: maxlimit=0.254 minlimit=0.09 mostfreqgap=0.13 toplayer_mingap=0.12 toplayer_maxgap=0.12 toplayer_prefgap=0.12 toplayer_minwidth=0.1 toplayer_maxwidth=0.1 toplayer_prefwidth=0.1 bottomlayer_mingap=0.12 bottomlayer_maxgap=0.12 bottomlayer_prefgap=0.12 bottomlayer_minwidth=0.1 bottomlayer_maxwidth=0.1 bottomlayer_prefwidth=0.1 impedanceprofiledriven=TRUE impedanceprofileid={E4FB221D-3FF4-46AB-B3B1-6676B59CEA93} impedanceprofilevalue=90.000000 maxuncoupledlength=12.7
DiffPairsRouting DiffPairsRouting_ETH_100R [InDifferentialPairClass('DPC_ETH_100R')] p9: maxlimit=0.254 minlimit=0.09 mostfreqgap=0.13 toplayer_mingap=0.16 toplayer_maxgap=0.16 toplayer_prefgap=0.16 toplayer_minwidth=0.09 toplayer_maxwidth=0.09 toplayer_prefwidth=0.09 bottomlayer_mingap=0.16 bottomlayer_maxgap=0.16 bottomlayer_prefgap=0.16 bottomlayer_minwidth=0.09 bottomlayer_maxwidth=0.09 bottomlayer_prefwidth=0.09 impedanceprofiledriven=TRUE impedanceprofileid={5106416E-43F8-41F8-8BCA-F68B3FB1C141} impedanceprofilevalue=100.000000 maxuncoupledlength=12.7
FanoutControl Fanout_BGA [IsBGA] p1: bgadir=Out bgaviamode=Closest fanoutstyle=Auto fanoutdirection=Alternating viagrid=0.025 // Fanout_BGA (Default Rule)
FanoutControl Fanout_LCC [IsLCC] p2: bgadir=Out bgaviamode=Closest fanoutstyle=Auto fanoutdirection=Alternating viagrid=0.025 // Fanout_LCC (Default Rule)
FanoutControl Fanout_SOIC [IsSOIC] p3: bgadir=Out bgaviamode=Closest fanoutstyle=Auto fanoutdirection=Alternating viagrid=0.025 // Fanout_SOIC (Default Rule)
FanoutControl Fanout_Small [(CompPinCount < 5)] p4: bgadir=Out bgaviamode=Closest fanoutstyle=Auto fanoutdirection=OutThenIn viagrid=0.025 // Fanout_Small (Default Rule)
FanoutControl Fanout_Default [All] p5: bgadir=Out bgaviamode=Closest fanoutstyle=Auto fanoutdirection=Alternating viagrid=0.025 // Fanout_Default (Default Rule)
HoleSize [All] p1: absolutevalues=TRUE maxlimit=10 minlimit=0.025 maxpercent=80.000 minpercent=20.000
HoleToHoleClearance [All] p1: gap=0.25 allowstackedmicrovias=TRUE
Length Length__SINGLE_SDMMC1_50R [InNetClass('NC_SINGLE_SDMMC1_50R')] p1: maxlimit=100 minlimit=0
Length Length__SINGLE_SDMMC2_50R [InNetClass('NC_SINGLE_SDMMC2_50R')] p2: maxlimit=50 minlimit=0
MatchedLengths MatchedLengths-ETH.RX1/3 [InxSignalClass('ETH1/3_RX')] p1: tolerance=5 checknetsindiffpair=FALSE checkdiffpairvsdiffpair=TRUE checkxsignals=TRUE checkothers=TRUE
MatchedLengths MatchedLengths-ETH.TX1/3 [InxSignalClass('ETH1/3_TX')] p2: tolerance=5 checknetsindiffpair=FALSE checkdiffpairvsdiffpair=TRUE checkxsignals=TRUE checkothers=TRUE
MatchedLengths MatchedLengths-ETH1/3_CLK [InxSignalClass('ETH1/3_CLK')] p3: tolerance=1 checknetsindiffpair=FALSE checkdiffpairvsdiffpair=TRUE checkxsignals=TRUE checkothers=TRUE
MatchedLengths MatchedLengths-EXTRA__LVDS_100R [InDifferentialPairClass('DPC_LVDS_100R')] p4: tolerance=5 checknetsindiffpair=FALSE checkdiffpairvsdiffpair=TRUE checkxsignals=TRUE checkothers=TRUE
MatchedLengths MatchedLengths-EXTRA__LVDS_100R_CON [InDifferentialPairClass('DPC_LVDS_100R_CON')] p5: tolerance=5 checknetsindiffpair=FALSE checkdiffpairvsdiffpair=TRUE checkxsignals=TRUE checkothers=TRUE
MatchedLengths MatchedLengths-EXTRA__PCIE_100R [InxSignalClass('DPX_PCIe')] p6: tolerance=5 checknetsindiffpair=FALSE checkdiffpairvsdiffpair=TRUE checkxsignals=TRUE checkothers=TRUE
MatchedLengths MatchedLengths-EXTRA__DSI_100R [InDifferentialPairClass('DPC_DSI_100R')] p7: tolerance=3 checknetsindiffpair=FALSE checkdiffpairvsdiffpair=TRUE checkxsignals=TRUE checkothers=TRUE
MatchedLengths MatchedLengths-INTRA__SINGLE_SDMMC1_50R [InNetClass('NC_SINGLE_SDMMC1_50R')] p8: tolerance=5 checknetsindiffpair=FALSE checkdiffpairvsdiffpair=TRUE checkxsignals=TRUE checkothers=TRUE
MatchedLengths MatchedLengths-INTRA__SINGLE_SDMMC2_50R [InNetClass('NC_SINGLE_SDMMC2_50R')] p9: tolerance=5 checknetsindiffpair=FALSE checkdiffpairvsdiffpair=TRUE checkxsignals=TRUE checkothers=TRUE
MatchedLengths MatchedLengths-INTRA__SINGLE_OCTOSPI_50R [InNetClass('NC_SINGLE_OCTOSPI_50R')] p10: tolerance=5 checknetsindiffpair=FALSE checkdiffpairvsdiffpair=TRUE checkxsignals=TRUE checkothers=TRUE
MatchedLengths MatchedLengths-EXTRA__CSI_100R [InDifferentialPairClass('DPC_CSI_100R')] p11: tolerance=1.3 checknetsindiffpair=FALSE checkdiffpairvsdiffpair=TRUE checkxsignals=TRUE checkothers=TRUE
MatchedLengths MatchedLengths-EXTRA__CSI_100R_CON [InDifferentialPairClass('DPC_CSI_100R_CON')] p12: tolerance=1.3 checknetsindiffpair=FALSE checkdiffpairvsdiffpair=TRUE checkxsignals=TRUE checkothers=TRUE
MaxMinImpedance "Schematic Impedance Constraint_3" [InNet('STLK_USB_CN_N')] p1: minimum=85.00 maximum=95.00
MaxMinImpedance "Schematic Impedance Constraint_2" [InNet('STLK_USB_P')] p2: minimum=85.00 maximum=95.00
MaxMinImpedance "Schematic Impedance Constraint_1" [InNet('STLK_USB_N')] p3: minimum=85.00 maximum=95.00
MaxMinImpedance "Schematic Impedance Constraint" [InNet('STLK_USB_CN_P')] p4: minimum=85.00 maximum=95.00
MinimumSolderMaskSliver [All] p1: minsoldermaskwidth=0.07
PlaneConnect [All] p1: planeconnectstyle=Direct reliefexpansion=0.508 reliefentries=4 reliefconductorwidth=0.21 reliefairgap=0.21
PolygonConnect PolygonConnect_Default [All] p1: thpad.connectstyle=Relief thpad.reliefconductorwidth=0.25 thpad.reliefentries=4 thpad.polygonreliefangle="90 Angle" thpad.airgapwidth=0.25 smdpad.connectstyle=NoConnect smdpad.reliefconductorwidth=0.2 smdpad.reliefentries=4 smdpad.polygonreliefangle="90 Angle" smdpad.airgapwidth=0.15 via.connectstyle=Direct via.reliefconductorwidth=0.2 via.reliefentries=4 via.polygonreliefangle="90 Angle" via.airgapwidth=0.2
RoomDefinition RoomDefinition_DDR [All] p1: confinementstyle=ConfineIn formatcopy=TRUE lockcomponents=FALSE outline 106.2,80.475 143.382,80.475 143.382,59.475 106.2,59.475
RoomDefinition RoomDefinition_eMMC [All] p2: confinementstyle=ConfineIn formatcopy=TRUE lockcomponents=FALSE outline 114.93,92.37 114.93,86.345 106.195,86.345 106.195,92.37
RoomDefinition RoomDefinition_MCU [All] p3: confinementstyle=ConfineIn formatcopy=TRUE lockcomponents=FALSE outline 81.172,84.475 106.072,84.475 106.072,60.475 81.172,60.475
RoutingLayers RoutingLayers_SINGLE_SDMMC1_50R [InNetClass('NC_SINGLE_SDMMC1_50R')] p1: top layer_v5=TRUE mid layer 1_v5=FALSE mid layer 2_v5=FALSE mid layer 3_v5=FALSE mid layer 4_v5=FALSE bottom layer_v5=TRUE
RoutingLayers RoutingLayers_SINGLE_SDMMC2_50R [InNetClass('NC_SINGLE_SDMMC2_50R')] p2: top layer_v5=TRUE mid layer 1_v5=FALSE mid layer 2_v5=FALSE mid layer 3_v5=FALSE mid layer 4_v5=FALSE bottom layer_v5=TRUE
RoutingLayers RoutingLayers_SINGLE_OCTOSPI_50R [InNetClass('NC_SINGLE_OCTOSPI_50R')] p3: top layer_v5=TRUE mid layer 1_v5=FALSE mid layer 2_v5=FALSE mid layer 3_v5=FALSE mid layer 4_v5=FALSE bottom layer_v5=TRUE
RoutingLayers RoutingLayers_SINGLE_DDR_55R [InNetClass('NC_SINGLE_DDR_55R')] p4: top layer_v5=TRUE mid layer 1_v5=FALSE mid layer 2_v5=FALSE mid layer 3_v5=FALSE mid layer 4_v5=FALSE bottom layer_v5=TRUE
RoutingLayers RoutingLayers_SINGLE_RGMII_ALL_50R_AND_CLK [InNetClass('NC_SINGLE_RGMII_ALL_50R_AND_CLK')] p5: top layer_v5=TRUE mid layer 1_v5=FALSE mid layer 2_v5=FALSE mid layer 3_v5=FALSE mid layer 4_v5=FALSE bottom layer_v5=TRUE
RoutingLayers RoutingLayers_I_SENS_XX_L3 [InNetClass('NC_I_SENS_XXX')] p6: top layer_v5=TRUE mid layer 1_v5=FALSE mid layer 2_v5=TRUE mid layer 3_v5=FALSE mid layer 4_v5=FALSE bottom layer_v5=TRUE
RoutingLayers [All] p7: top layer_v5=TRUE mid layer 1_v5=TRUE mid layer 2_v5=TRUE mid layer 3_v5=TRUE mid layer 4_v5=TRUE bottom layer_v5=TRUE
RoutingVias RoutingVias_Default [All] p1: holewidth=0.15 width=0.4 viastyle="Through Hole" minholewidth=0.15 minwidth=0.4 maxholewidth=0.35 maxwidth=0.6 viatemplateguid#1={5DDA59CE-75AD-463D-953D-41E5DFD22A90} viatemplateguid#2={40F6E5AB-E602-4A5B-B1FB-D504E8CD151B} viatemplateguid#3={5FB3A576-9C61-40FB-A114-9033EB4BA092} viatemplateguid#4={BB8F4C89-420F-4EBC-9772-FD82009DE81A} viatemplateguid#5={3FF096CA-B7A5-4E0B-A50A-8B2CD18CCC19} viatemplatename#1=v50h25m30mx30 viatemplatename#2=v55h35m40mx40 viatemplatename#3=v40h20m0mx0 viatemplatename#4=v40h20m25mx25 viatemplatename#5=v50h25m0mx0
ShortCircuit ShortCircuit_I-SENS-VDDCORE_N [InNet('I_SENS_VDDCORE_N') vs InNet('VDDCORE')] p1: allowed=TRUE
ShortCircuit ShortCircuit_I-SENS-VDDGPU_N [InNet('I_SENS_VDDGPU_N') vs InNet('VDDGPU')] p2: allowed=TRUE
ShortCircuit ShortCircuit_I-SENS-VDDIO_N [InNet('I_SENS_VDDIO_N') vs InNet('VDDIO')] p3: allowed=TRUE
ShortCircuit ShortCircuit_I-SENS-VDDCPU_N [InNet('I_SENS_VDDCPU_N') vs InNet('VDDCPU')] p4: allowed=TRUE
ShortCircuit ShortCircuit_VDD_DDR [InNet('VDD_DDR') And OnLayer('Top Layer') vs InNet('I_SENS_VDD_DDR_4_N') And OnLayer('Top Layer')] p5: allowed=TRUE
ShortCircuit ShortCircuit_Link200 [InPadClass('PC_LINK200')] p6: allowed=TRUE
SilkToSilkClearance [All] p1: silktosilkclearance=0.2
SilkToSolderMaskClearance [IsPad] p1: minsilkscreentomaskgap=0.015 clearancetoexposedcopper=TRUE
SolderMaskExpansion [All] p1: expansion=0.1 istentingtop=FALSE
ViasUnderSMD [InPadClass('PC_VIAS-IN-PAD_OK')] p1: allowed=TRUE
Width Width_SINGLE_50R [InNetClass('NC_SINGLE_SDMMC1_50R') or  InNetClass('NC_SINGLE_SDMMC2_50R') or InNetClass('NC_SINGLE_OCTOSPI_50R') or InNetClass('NC_SINGLE_RGMII_ALL_50R_AND_CLK')] p1: maxlimit=0.199 minlimit=0.078 preferedwidth=0.199 toplayer_minwidth=0.09 toplayer_maxwidth=0.11 toplayer_prefwidth=0.11 bottomlayer_minwidth=0.09 bottomlayer_maxwidth=0.11 bottomlayer_prefwidth=0.11 impedanceprofiledriven=TRUE impedanceprofileid={BF206F84-D843-4EED-AB36-0A4DAE8FF78E} impedanceprofilevalue=50.000000 minimp=50.000000 maximp=50.000000 favimp=50.000000
Width Width_SINGLE_DDR_55R [InNetClass('NC_SINGLE_DDR_55R')] p2: maxlimit=0.199 minlimit=0.078 preferedwidth=0.199 toplayer_minwidth=0.09 toplayer_maxwidth=0.09 toplayer_prefwidth=0.09 bottomlayer_minwidth=0.09 bottomlayer_maxwidth=0.09 bottomlayer_prefwidth=0.09 impedanceprofiledriven=TRUE impedanceprofileid={AA24371C-465E-452F-8EAC-78B770D9C87C} impedanceprofilevalue=55.000000 minimp=50.000000 maximp=50.000000 favimp=50.000000
Width Width_Default [InNetClass('All Nets')] p3: maxlimit=10 minlimit=0.09 preferedwidth=0.1 midlayer1_minwidth=0.1 midlayer2_minwidth=0.1 midlayer3_minwidth=0.1 midlayer4_minwidth=0.1 minimp=50.000000 maximp=50.000000 favimp=50.000000
15 further rules are at their usual default settings.

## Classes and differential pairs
component class "U_Expansion _&_mikroBUS_Connectors": C62 C69 CN5 CN25 R94 R243 R244 R289 U53
component class U_USB_HUB: C115 C119 C126 C128 C143 C146 C150 C155 C161 C163 C273 C275 C276 C277 C283 C284 C285 CN19 L12 LD12 R95 R97 R98 R99 R100 R101 R102 R103 R104 R105 R106 R157 R170 R323 R324 TP32 U34 U41 U44 U45 U46 U51 X3
differential pair class DPC_CSI_100R_CON: CSI.CKcon CSI.D0con CSI.D1con
differential pair class DPC_LVDS_100R: LVDS1.CLK LVDS1.D0 LVDS1.D1 LVDS1.D2 LVDS1.D3
net class NC_SINGLE_OCTOSPI_50R: QSPI1.CLK QSPI1.IO0 QSPI1.IO1 QSPI1.IO2 QSPI1.IO3 QSPI1.NCS1
differential pair class DPC_ETH_100R: RJ451_D1 RJ451_D2 RJ451_D3 RJ451_D4 RJ452_D1 RJ452_D2 RJ452_D3 RJ452_D4 RJ453_D1 RJ453_D2 RJ453_D3 RJ453_D4
net class NC_SINGLE_SDMMC2_50R: eMMC.SDMMC2_CK eMMC.SDMMC2_CMD eMMC.SDMMC2_D0 eMMC.SDMMC2_D1 eMMC.SDMMC2_D2 eMMC.SDMMC2_D3 eMMC.SDMMC2_D4 eMMC.SDMMC2_D5 eMMC.SDMMC2_D6 eMMC.SDMMC2_D7
net class NC_SINGLE_SDMMC1_50R: NetCN1_5 SD.SDMMC1_CK SD.SDMMC1_CMD SD.SDMMC1_D0 SD.SDMMC1_D1 SD.SDMMC1_D2 SD.SDMMC1_D3
net class NC_SINGLE_DDR_55R: DDR_A0 DDR_A1 DDR_A2 DDR_A3 DDR_A4 DDR_A5 DDR_A6 DDR_A7 DDR_A8 DDR_A9 DDR_A10 DDR_A11 DDR_A12 DDR_A13 DDR_ACTN DDR_BA0 DDR_BA1 DDR_BG0 DDR_CASN DDR_CKE DDR_CSN DDR_DQ0 DDR_DQ1 DDR_DQ2 DDR_DQ3 DDR_DQ4 DDR_DQ5 DDR_DQ6 DDR_DQ7 DDR_DQ8 DDR_DQ9 DDR_DQ10 DDR_DQ11 DDR_DQ12 DDR_DQ13 DDR_DQ14 DDR_DQ15 DDR_DQ16 DDR_DQ17 DDR_DQ18 DDR_DQ19 DDR_DQ20 DDR_DQ21 DDR_DQ22 DDR_DQ23 DDR_DQ24 DDR_DQ25 DDR_DQ26 DDR_DQ27 DDR_DQ28 DDR_DQ29 DDR_DQ30 DDR_DQ31 DDR_DQM0 DDR_DQM1 DDR_DQM2 DDR_DQM3 DDR_ODT DDR_RASN DDR_WEN
net class NC_SINGLE_RGMII_ALL_50R_AND_CLK: ETH1.CLK ETH1.CLK125 ETH1.GTX_CLK ETH1.MDC ETH1.MDINT ETH1.MDIO ETH1.RX_CLK ETH1.RX_CTL ETH1.RXD0 ETH1.RXD1 ETH1.RXD2 ETH1.RXD3 ETH1.TX_CTL ETH1.TXD0 ETH1.TXD1 ETH1.TXD2 ETH1.TXD3 ETH1i.CLK125 ETH2.CLK ETH2.CLK125 ETH2.GTX_CLK ETH2.MDC ETH2.MDINT ETH2.MDIO ETH2.RX_CLK ETH2.RX_CTL ETH2.RXD0 ETH2.RXD1 ETH2.RXD2 ETH2.RXD3 ETH2.TX_CTL ETH2.TXD0 ETH2.TXD1 ETH2.TXD2 ETH2.TXD3 ETH3.GTX_CLK ETH3.MDINT ETH3.RX_CLK ETH3.RX_CTL ETH3.RXD0 ETH3.RXD1 ETH3.RXD2 ETH3.RXD3 ETH3.TX_CTL ETH3.TXD0 ETH3.TXD1 ETH3.TXD2 ETH3.TXD3 NetR141_2 NetR142_2 NetR143_2 NetR144_2 NetR145_2 NetR146_2 NetR161_2 NetR162_2 NetR163_2 NetR164_2 NetR165_2 NetR166_2 NetR167_2 NetR168_2 NetR169_2 NetR173_2 NetR174_2 NetR175_2 NetR177_2 NetR178_2 NetR179_2 NetR180_2 NetR185_2 NetR186_2 NetR187_2 NetR189_2 NetR262_2
net class NC_BUS_JTAG: JTCK_SWCLK JTDI JTDO_SWDO JTMS_SWDIO
differential pair class DPC_CSI_100R: CSI.CK CSI.D0 CSI.D1
differential pair class DPC_LVDS_100R_CON: LVDS1.CLKcon LVDS1.D0con LVDS1.D1con LVDS1.D2con LVDS1.D3con
differential pair class DPC_USB_90R: PCIE.USB STLK_USB STLK_USB_CN USB1CN USB2CN USB_DCONN USBDN2 USBDN3 USBDR USBH
differential pair class DPC_PCIE_100R: 100MCLK0 100MCLK1 COMBOTX1 PCIE.CLKIN PCIE.CLKOUT PCIE.RX1 PCIE.TX1 PCIE_CLKOUT
differential pair class DPC_DSI_100R: DSI.CK DSI.D0 DSI.D1 DSI.D2 DSI.D3
differential pair class DPC_DDR_100R: DDR_CLK DDR_DQS0 DDR_DQS1 DDR_DQS2 DDR_DQS3
net class NC_DP_DDR_100R: DDR_CLK_N DDR_CLK_P DDR_DQS0_N DDR_DQS0_P DDR_DQS1_N DDR_DQS1_P DDR_DQS2_N DDR_DQS2_P DDR_DQS3_N DDR_DQS3_P
net class NC_DP_USB_90R: PCIE.USB_N PCIE.USB_P STLK_USB_CN_N STLK_USB_CN_P STLK_USB_N STLK_USB_P USB1CN_N USB1CN_P USB2CN_N USB2CN_P USB_DCONN_N USB_DCONN_P USBDN2_N USBDN2_P USBDN3_N USBDN3_P USBDR_N USBDR_P USBH_N USBH_P
net class SD.SDMMC1_D[0..3]: SD.SDMMC1_D0 SD.SDMMC1_D1 SD.SDMMC1_D2 SD.SDMMC1_D3
net class QSPI1.IO[0..3]: QSPI1.IO0 QSPI1.IO1 QSPI1.IO2 QSPI1.IO3
net class ETH3.TXD[0..3]: ETH3.TXD0 ETH3.TXD1 ETH3.TXD2 ETH3.TXD3
net class ETH3.RXD[0..3]: ETH3.RXD0 ETH3.RXD1 ETH3.RXD2 ETH3.RXD3
net class ETH2.TXD[0..3]: ETH2.TXD0 ETH2.TXD1 ETH2.TXD2 ETH2.TXD3
net class ETH2.RXD[0..3]: ETH2.RXD0 ETH2.RXD1 ETH2.RXD2 ETH2.RXD3
net class ETH1.TXD[0..3]: ETH1.TXD0 ETH1.TXD1 ETH1.TXD2 ETH1.TXD3
net class ETH1.RXD[0..3]: ETH1.RXD0 ETH1.RXD1 ETH1.RXD2 ETH1.RXD3
net class eMMC.SDMMC2_D[0..7]: eMMC.SDMMC2_D0 eMMC.SDMMC2_D1 eMMC.SDMMC2_D2 eMMC.SDMMC2_D3 eMMC.SDMMC2_D4 eMMC.SDMMC2_D5 eMMC.SDMMC2_D6 eMMC.SDMMC2_D7
net class BOOT[0..3]: BOOT0 BOOT1 BOOT2 BOOT3
net class ARD_D[0..15]: EXP_GPIO2 EXP_GPIO3
component class U_Video: C1 C2 C3 C4 C7 C9 C10 C174 CN2 CN3 CN4 R1 R2 R5 R9 R18 R250 R251 SB1 TP1 TP2 TP3 TP4 TP5 TP6 TP7 U1 U2 U3 U4 U5 U6 U7 U11 U12 U13 U14 U15 U16 U17 U18
component class U_USB_PCIe: C97 C98 C101 C102 C156 C159 C162 C168 C170 C171 C265 C266 C267 C268 C269 C272 C274 C334 C335 CN13 HW8 HW9 HW10 HW11 LD10 LED2 Q4 Q5 R77 R78 R82 R83 R84 R85 R87 R88 R89 R90 R91 R92 R171 R172 R219 R220 R223 R225 R231 R232 R274 R285 R287 R290 R291 R325 R326 TP14 TP15 TP16 TP17 TP18 TP19 TP20 TP21 TP23 TP24 TP25 TP34 TP36 TP37 TP38 TP39 U33 U42 U43 U50
component class U_2_DDR4_16bits: C48 C49 C50 C51 C77 C78 C79 C80 C82 C83 C84 C85 C93 C94 C95 C99 C183 C184 C185 C186 C187 C188 C189 C198 C202 C211 C226 C236 C238 C239 C245 C247 C254 C255 C256 C257 C258 C259 C261 C262 C264 CN3 R63 R73 R252 R253 R254 R255 R256 R257 R258 R259 R262 R263 R264 R265 R266 R268 R270 R271 R273 R275 R276 R277 R278 R279 R280 R281 R282 R283 R284 TP10 U29
component class U_STLINK_V3EC: C110 C129 C131 C132 C133 C140 C145 C149 C157 C158 C160 C164 C165 C166 C169 C172 C173 C176 C281 C282 C289 C290 C297 C298 C299 C303 C310 C311 C324 C325 C326 C327 C328 C329 C333 CN14 D2 D3 JP3 LD5 LD6 LNK13 R129 R130 R131 R132 R133 R134 R153 R154 R155 R156 R181 R194 R207 R209 R211 R212 R213 R214 R215 R216 R217 R218 R221 R222 R226 R227 R229 R230 R239 R240 R241 R242 TP26 TP27 TP28 TP29 TP33 U35 U36 U47 U48 U49 U52 X7
component class U_SDcard_eMMC: C6 C8 C177 C178 C179 C180 C181 C182 CN1 D5 HW7 R6 R10 R11 R12 R13 R14 R15 R37 R44 R49 R247 R248 TP9 U8 U9 U24
component class U_QSPI_NOR: C175 D1 R21 R22 R23 R33 U22
component class U_Power_MPU: C87 C88 C190 C191 C192 C193 C194 C195 C196 C197 C199 C200 C201 C203 C204 C205 C206 C207 C208 C209 C210 C212 C213 C214 C215 C216 C217 C218 C219 C220 C221 C222 C223 C224 C225 C227 C228 C229 C230 C231 C232 C233 C234 C235 C237 C240 C241 C242 C243 C244 C246 C248 C249 C250 C251 C252 C253 C260 CN12 D6 R66 R67 R249 R267 R269 R286 TP22
component class U_Power_PMIC: B2 C5 C16 C17 C18 C19 C20 C21 C22 C23 C24 C25 C26 C27 C28 C29 C30 C31 C32 C33 C34 C35 C36 C37 C38 C39 C40 C41 C42 C43 C44 C45 C46 C47 C52 C53 C54 C55 C56 C57 C58 C59 C60 C61 C63 C64 C65 C66 C67 C68 C70 C71 C72 C73 C74 C75 C76 C89 C114 C116 C117 C118 C127 C130 C147 C148 C151 CN10 CN20 F1 HW1 JP4 L1 L2 L3 L4 L5 L6 L7 L8 LD11 LNK1 LNK2 LNK3 LNK4 LNK5 LNK6 LNK7 LNK8 LNK9 LNK10 LNK11 LNK12 R35 R36 R38 R39 R41 R42 R43 R45 R46 R47 R48 R51 R52 R53 R54 R55 R56 R57 R58 R59 R60 R61 R62 R65 R69 R204 R208 R210 TP8 U26 U30 U37
component class U_Peripherals: B1 B3 B4 B5 C11 C12 C13 CN6 CN7 CN8 HW2 HW3 HW4 HW5 HW6 HW1301 HW1302 HW1303 LD1 LD2 LD12 Q1 Q2 Q3 R3 R4 R7 R8 R16 R17 R19 R20 R24 R25 R26 R28 R29 R30 R68 R71 R76 R79 SW1 U10 U19 U20 U21
component class U_MP257_18x18: C81 C86 C90 C91 C92 CN3 CN22 R27 R31 R32 R64 R70 R72 R74 R75 R107 R125 R205 R206 R224 R228 R245 R246 R260 R261 R272 TP11 TP12 TP13 TP30 TP35 X1 X2
component class U_FDCAN: C14 C15 C96 C100 CN9 CN11 JP1 JP2 R34 R40 R50 R80 R81 R86 SB2 SB3 U23 U25 U31 U32
component class U_Ethernet3: C106 C107 C108 C113 C122 C125 C136 C139 C144 C154 C278 C286 C291 C292 C300 C304 C307 C312 C315 C318 C319 C330 CN18 L11 L13 LD9 LE3 R119 R120 R121 R122 R123 R124 R128 R147 R148 R149 R150 R151 R152 R160 R163 R166 R169 R175 R180 R184 R187 R190 R193 R198 R201 R203 R237 R238 R297 R298 R299 R306 R307 R308 R311 R314 R315 R320 TP31 U40 X6
component class U_Ethernet2: C103 C104 C109 C111 C120 C123 C134 C137 C141 C152 C280 C288 C295 C296 C302 C306 C309 C314 C317 C322 C323 C332 CN16 L9 L15 LD7 LE1 R109 R110 R111 R112 R113 R114 R126 R135 R136 R137 R138 R139 R140 R158 R161 R164 R167 R173 R176 R178 R182 R185 R188 R191 R195 R196 R199 R233 R234 R292 R293 R303 R304 R305 R310 R313 R318 R319 R322 U38 X4
component class U_Ethernet1: C105 C112 C121 C124 C135 C138 C142 C153 C270 C271 C279 C287 C293 C294 C301 C305 C308 C313 C316 C320 C321 C331 CN17 L10 L14 LD8 LE2 R93 R108 R115 R116 R117 R118 R127 R141 R142 R143 R144 R145 R146 R159 R162 R165 R168 R174 R177 R179 R183 R186 R189 R192 R197 R200 R202 R235 R236 R294 R295 R296 R300 R301 R302 R309 R312 R316 R317 R321 U39 X5
pad class PC_VIAS-IN-PAD_OK: U121-25 U801-15 U5002-9 U9000-21
pad class PC_LINK200: LNK4000-1 LNK4000-2 LNK4001-1 LNK4001-2 LNK4002-1 LNK4002-2 LNK4004-1 LNK4004-2 LNK4005-1 LNK4005-2 LNK4006-1 LNK4006-2 LNK4007-1 LNK4007-2 LNK4008-1 LNK4008-2 LNK4009-1 LNK4009-2
differential pair LVDS1.D3con: +LVDS1.D3con_P -LVDS1.D3con_N
differential pair LVDS1.D2con: +LVDS1.D2con_P -LVDS1.D2con_N
differential pair LVDS1.D1con: +LVDS1.D1con_P -LVDS1.D1con_N
differential pair LVDS1.D0con: +LVDS1.D0con_P -LVDS1.D0con_N
differential pair LVDS1.CLKcon: +LVDS1.CLKcon_P -LVDS1.CLKcon_N
differential pair CSI.D1con: +CSI.D1con_P -CSI.D1con_N
differential pair CSI.D0con: +CSI.D0con_P -CSI.D0con_N
differential pair CSI.CKcon: +CSI.CKcon_P -CSI.CKcon_N
differential pair USBDR: +USBDR_P -USBDR_N
differential pair USBDN3: +USBDN3_P -USBDN3_N
differential pair USBDN2: +USBDN2_P -USBDN2_N
differential pair USB_DCONN: +USB_DCONN_P -USB_DCONN_N
differential pair USB2CN: +USB2CN_P -USB2CN_N
differential pair USB1CN: +USB1CN_P -USB1CN_N
differential pair STLK_USB: +STLK_USB_P -STLK_USB_N
differential pair STLK_USB_CN: +STLK_USB_CN_P -STLK_USB_CN_N
differential pair RJ453_D4: +RJ453_D4_P -RJ453_D4_N
differential pair RJ453_D3: +RJ453_D3_P -RJ453_D3_N
differential pair RJ453_D2: +RJ453_D2_P -RJ453_D2_N
differential pair RJ453_D1: +RJ453_D1_P -RJ453_D1_N
differential pair RJ452_D4: +RJ452_D4_P -RJ452_D4_N
differential pair RJ452_D3: +RJ452_D3_P -RJ452_D3_N
differential pair RJ452_D2: +RJ452_D2_P -RJ452_D2_N
differential pair RJ452_D1: +RJ452_D1_P -RJ452_D1_N
differential pair RJ451_D4: +RJ451_D4_P -RJ451_D4_N
differential pair RJ451_D3: +RJ451_D3_P -RJ451_D3_N
differential pair RJ451_D2: +RJ451_D2_P -RJ451_D2_N
differential pair RJ451_D1: +RJ451_D1_P -RJ451_D1_N
differential pair PCIE_CLKOUT: +PCIE_CLKOUT_P -PCIE_CLKOUT_N
differential pair PCIE.USB: +PCIE.USB_P -PCIE.USB_N
differential pair PCIE.CLKIN: +PCIE.CLKIN_P -PCIE.CLKIN_N
differential pair LVDS1.CLK: +LVDS1.CLK_P -LVDS1.CLK_N
differential pair DDR_DQS3: +DDR_DQS3_P -DDR_DQS3_N
differential pair DDR_DQS2: +DDR_DQS2_P -DDR_DQS2_N
differential pair DDR_DQS1: +DDR_DQS1_P -DDR_DQS1_N
differential pair DDR_DQS0: +DDR_DQS0_P -DDR_DQS0_N
differential pair DDR_CLK: +DDR_CLK_P -DDR_CLK_N
differential pair COMBOTX1: +COMBOTX1_P -COMBOTX1_N
differential pair 100MCLK1: +100MCLK1_P -100MCLK1_N
differential pair 100MCLK0: +100MCLK0_P -100MCLK0_N
differential pair USBH: +USBH_P -USBH_N
differential pair PCIE.TX1: +PCIE.TX1_P -PCIE.TX1_N
differential pair PCIE.RX1: +PCIE.RX1_P -PCIE.RX1_N
differential pair PCIE.CLKOUT: +PCIE.CLKOUT_P -PCIE.CLKOUT_N
differential pair LVDS1.D3: +LVDS1.D3_P -LVDS1.D3_N
differential pair LVDS1.D2: +LVDS1.D2_P -LVDS1.D2_N
differential pair LVDS1.D1: +LVDS1.D1_P -LVDS1.D1_N
differential pair LVDS1.D0: +LVDS1.D0_P -LVDS1.D0_N
differential pair DSI.D3: +DSI.D3_P -DSI.D3_N
differential pair DSI.D2: +DSI.D2_P -DSI.D2_N
differential pair CSI.D1: +CSI.D1_P -CSI.D1_N
differential pair CSI.D0: +CSI.D0_P -CSI.D0_N
differential pair CSI.CK: +CSI.CK_P -CSI.CK_N
differential pair DSI.D1: +DSI.D1_P -DSI.D1_N
differential pair DSI.D0: +DSI.D0_P -DSI.D0_N
differential pair DSI.CK: +DSI.CK_P -DSI.CK_N

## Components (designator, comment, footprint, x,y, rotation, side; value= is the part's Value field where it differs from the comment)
B1 "SW_PUSH_SMD" SWI_KNITTER_TSS644S 15.048,122.7 r180 top value=SW-PUSH-TSS644S
B2 "SW_PUSH_SMD" SWI_KNITTER_TSS644S 27.048,122.7 r0 top value=SW-PUSH-TSS644S
B3 "SW_PUSH_SMD" SWI_KNITTER_TSS644S 6.787,112.55 r180 top value=SW-PUSH-TSS644S
B4 "SW_PUSH_SMD" SWI_KNITTER_TSS644S 19.787,112.55 r0 top value=SW-PUSH-TSS644S
B5 "SW_PUSH_SMD" SWI_KNITTER_TSS644S 32.788,112.55 r0 top value=SW-PUSH-TSS644S
C1 "Capacitor" C0402 136.75,127.796 r180 top value=100nF
C2 "Capacitor" C0402 129.85,127.775 r0 top value=100nF
C3 "Capacitor" C0402 40.55,126.8 r180 top value=100nF
C4 "Capacitor" C0805 40.35,125.475 r180 top value=47uF
C5 "Capacitor" C0402 32.675,120.9 r270 top value=10nF
C6 "Capacitor" C0402 154.5,120.48 r180 top value=4.7uF
C7 "Capacitor" C0402 80.2,119.6 r180 top value=1uF
C8 "Capacitor" C0402 153.625,116.925 r0 top value=100nF
C9 "Capacitor" C0402 127.573,115.875 r180 top value=100nF
C10 "Capacitor" C0805 127.973,114.475 r180 top value=47uF
C11 "Capacitor" C0402 15.363,104.975 r0 top value=100nF
C12 "Capacitor" C0402 28.363,104.975 r0 top value=100nF
C13 "Capacitor" C0402 2.362,107.375 r0 top value=1nF
C14 "Capacitor" C0402 21.044,102.946 r180 top value=100nF
C15 "Capacitor" C0402 18.869,95.911 r90 top value=100nF
C16 "Capacitor" C0805 43.5,88.627 r270 top value=22uF
C17 "Capacitor" C0805 45.35,88.627 r270 top value=22uF
C18 "Capacitor" C0805 47.2,88.627 r270 top value=22uF
C19 "Capacitor" C0603 50.155,89.277 r180 top value=22uF
C20 "Capacitor" C0603 61.93,88.752 r180 top value=22uF
C21 "Capacitor" C0603 55.15,87.902 r270 top value=22uF
C22 "Capacitor" C0603 56.425,87.902 r270 top value=22uF
C23 "Capacitor" C0603 57.7,87.902 r270 top value=22uF
C24 "Capacitor" C0603 58.975,87.902 r270 top value=22uF
C25 "Capacitor" C0603 35.945,87.852 r0 top value=22uF
C26 "Capacitor" C0603 38.9,87.052 r270 top value=22uF
C27 "Capacitor" C0603 40.2,87.052 r270 top value=22uF
C28 "Capacitor" C0603 41.5,87.052 r270 top value=22uF
C29 "Capacitor" C0603 43.225,84.552 r270 top value=10uF
C30 "Capacitor" C0603 45.45,83.902 r0 top value=10uF
C31 "Capacitor" C0603 33.675,83.277 r270 top value=22uF
C32 "Capacitor" C0603 53.8,82.827 r180 top value=10uF
C33 "Capacitor" C0603 63.455,82.777 r180 top value=22uF
C34 "Capacitor" C0603 56.6,81.927 r270 top value=22uF
C35 "Capacitor" C0603 57.9,81.927 r270 top value=22uF
C36 "Capacitor" C0603 59.2,81.927 r270 top value=22uF
C37 "Capacitor" C0603 60.5,81.927 r270 top value=22uF
C38 "Capacitor" C0603 53.775,81.402 r180 top value=10uF
C39 "Capacitor" C0402 40.725,81.402 r0 top value=10uF
C40 "Capacitor" C0402 40.725,80.577 r0 top value=10uF
C41 "Capacitor" C0603 34.475,79.877 r0 top value=22uF
C42 "Cap_POL_TANA" CPOL_TCJ-B_1210_H210 25.875,78.675 r180 top value=100uF
C43 "Capacitor" C0402 37.735,79.627 r180 top value=1uF
C44 "Capacitor" C0603 34.475,78.577 r0 top value=22uF
C45 "Capacitor" C0603 41.375,77.427 r90 top value=10uF
C46 "Capacitor" C0603 54.2,77.452 r180 top value=10uF
C47 "Capacitor" C0603 34.475,77.277 r0 top value=22uF
C48 "Capacitor" C0402 135.125,76.5 r0 top value=100nF
C49 "Capacitor" C0402 130.675,76.375 r0 top value=100nF
C50 "Capacitor" C0402 132.375,76.375 r180 top value=100nF
C51 "Capacitor" C0402 128.645,76.365 r0 top value=100nF
C52 "Capacitor" C0805 57.5,75.077 r270 top value=22uF
C53 "Capacitor" C0805 59.3,75.077 r270 top value=22uF
C54 "Capacitor" C0805 61.1,75.077 r270 top value=22uF
C55 "Capacitor" C0603 64.055,75.727 r180 top value=22uF
C56 "Capacitor" C0603 40.3,75.152 r270 top value=10uF
C57 "Capacitor" C0805 32.8,74 r270 top value=22uF
C58 "Capacitor" C0805 34.6,74 r270 top value=22uF
C59 "Capacitor" C0805 36.4,74 r270 top value=22uF
C60 "Capacitor" C0805 38.2,74 r270 top value=22uF
C61 "Capacitor" C0402 50.825,73.877 r90 top value=4.7uF
C62 "Capacitor" C0402 161.7,66.225 r270 top value=100nF
C63 "Capacitor" C0402 43.95,72.727 r270 top value=4.7uF
C64 "Capacitor" C0402 47.375,72.427 r90 top value=1uF
C65 "Capacitor" C0402 54.45,72.372 r270 top value=4.7uF
C66 "Capacitor" C0402 52.4,71.875 r90 top value=4.7uF
C67 "Capacitor" C0402 53.225,71.877 r90 top value=1uF
C68 "Capacitor" C0402 49.55,71.727 r90 top value=4.7uF
C69 "Capacitor" C0402 170.125,64.65 r90 top value=100nF
C70 "Capacitor" C0402 44.725,71.522 r90 top value=1uF
C71 "Capacitor" C0603 51.05,70.527 r90 top value=4.7uF
C72 "Capacitor" C0402 45.975,70.827 r270 top value=4.7uF
C73 "Capacitor" C0402 46.8,70.627 r270 top value=4.7uF
C74 "Capacitor" C0402 48.05,69.927 r270 top value=4.7uF
C75 "Capacitor" C0402 48.875,69.927 r270 top value=4.7uF
C76 "Capacitor" C0603 153.75,69.925 r0 top value=10uF
C77 "Capacitor" C0402 111.075,69.3 r0 top value=100nF
C78 "Capacitor" C0402 113,69.25 r0 top value=100nF
C79 "Capacitor" C0402 114.925,69.25 r180 top value=100nF
C80 "Capacitor" C0402 116.725,69.25 r0 top value=100nF
C81 "Capacitor" C0402 77.85,67.85 r90 top value=6.8pF
C82 "Capacitor" C0402 139.225,67.55 r0 top value=100nF
C83 "Capacitor" C0402 129.275,67.45 r0 top value=100nF
C84 "Capacitor" C0402 132.5,67.45 r180 top value=100nF
C85 "Capacitor" C0603 138.225,66.425 r180 top value=10uF
C86 "Capacitor" C0402 77.85,65.45 r270 top value=6.8pF
C87 "" C0402 74.062,64.225 r270 top value=100nF
C88 "Capacitor" C0402 67.475,60.85 r270 top value=2.2uF
C89 "Capacitor" C0603 153.755,64.225 r0 top value=10uF
C90 "Capacitor" C0402 77.65,62.15 r270 top value=6.8pF
C91 "Capacitor" C0402 74.55,62.025 r270 top value=10nF
C92 "Capacitor" C0402 74.55,60.325 r270 top value=6.8pF
C93 "Capacitor" C0402 120.15,60.425 r0 top value=100nF
C94 "Capacitor" C0402 114.844,60.422 r180 top value=100nF
C95 "Capacitor" C0402 111,60.4 r0 top value=100nF
C96 "Capacitor" C0402 24.44,57.845 r0 top value=100nF
C97 "Capacitor" C0201_MURATA_GRM033_H0P3 100.325,59.75 r270 top value=100nF
C98 "Capacitor" C0201_MURATA_GRM033_H0P3 101.025,59.75 r270 top value=100nF
C99 "Capacitor" C0603 120.125,59.39 r0 top value=10uF
C100 "Capacitor" C0402 31.475,55.67 r90 top value=100nF
C101 "Capacitor" C0402 103.525,46.74 r270 top value=100nF
C102 "Capacitor" C0402 104.425,46.74 r270 top value=100nF
C103 "" C0402 63.625,36.17 r0 top value=100nF
C104 "" C0402 66.175,36.17 r180 top value=100nF
C105 "" C0402 88.625,36.17 r0 top value=100nF
C106 "" C0402 113.625,36.17 r0 top value=100nF
C107 "" C0402 115.975,36.17 r180 top value=100nF
C108 "" C0402 117.605,36.17 r0 top value=100nF
C109 "" C0402 67.825,36.15 r0 top value=100nF
C110 "Capacitor" C0805 30.725,34.225 r0 top value=2.2uF
C111 "" C0603 60.62,34.07 r180 top value=22uF
C112 "" C0603 85.62,34.07 r180 top value=22uF
C113 "" C0603 110.62,34.07 r0 top value=22uF
C114 "Capacitor" C0805 7.275,33.65 r0 top value=47uF
C115 "Capacitor" C0402 122.625,31.95 r270 top value=6.8pF
C116 "Capacitor" C0805_H0P85 15.55,31.25 r270 top value=100nF
C117 "Capacitor" C0805 17.35,31.25 r270 top value=10uF
C118 "Capacitor" C0805 7.275,31.625 r0 top value=47uF
C119 "Capacitor" C0402 132.761,32 r180 top value=100nF
C120 "" C0603 61.275,31.175 r90 top value=22uF
C121 "" C0603 86.275,31.175 r90 top value=22uF
C122 "" C0603 111.275,31.175 r90 top value=22uF
C123 "" C0402 60.15,31.425 r90 top value=100nF
C124 "" C0402 85.15,31.425 r90 top value=100nF
C125 "" C0402 110.15,31.425 r90 top value=100nF
C126 "Capacitor" C0402 122.625,30.25 r90 top value=6.8pF
C127 "Cap_POL_TANA" CPOL_WURTH_WCAP-ASLL_8X10P5 6.85,23.925 r270 top value=100uF
C128 "Capacitor" C0402 122.75,28.9 r0 top value=100nF
C129 "Capacitor" C0603 30.87,28.4 r0 top value=10uF
C130 "Capacitor" C0402 17.35,28.15 r90 top value=22pF
C131 "Capacitor" C0402 48.45,27.85 r270 top value=20pF
C132 "Capacitor" C0402 46.475,27.125 r180 top value=2.2uF
C133 "Capacitor" C0402 33.395,25.925 r90 top value=2.7pF
C134 "" C0402 54.85,25.9 r270 top value=10pF
C135 "" C0402 79.85,25.9 r270 top value=10pF
C136 "" C0402 104.85,25.9 r270 top value=10pF
C137 "" C0402 54.85,24.25 r90 top value=10pF
C138 "" C0402 79.85,24.25 r90 top value=10pF
C139 "" C0402 104.85,24.25 r90 top value=10pF
C140 "Capacitor" C0402 33.395,24.225 r90 top value=2.7pF
C141 "" C0402 67.9,23.1 r90 top value=100nF
C142 "" C0402 93.35,23.45 r180 top value=100nF
C143 "Capacitor" C0805 122.375,22.4 r90 top value=47uF
C144 "" C0402 117.9,22.9 r90 top value=100nF
C145 "Capacitor" C0402 46.475,23.125 r180 top value=2.2uF
C146 "Capacitor" C0402 124.025,22.6 r90 top value=100nF
C147 "Cap_POL_TANA" CPOL_TCJ-B_1210_H210 149.65,21.575 r0 top value=100uF
C148 "Capacitor" C0805 13.725,21.75 r90 top value=10uF
C149 "Capacitor" C0402 30.95,21.775 r90 top value=100nF
C150 "Capacitor" C1206_H1P6 134.15,19.65 r270 top value=220uF
C151 "Capacitor" C0402 15.475,21.225 r180 top value=100pF
C152 "" C0402 61.365,19.625 r270 top value=100nF
C153 "" C0402 86.365,19.625 r270 top value=100nF
C154 "" C0402 111.365,19.625 r270 top value=100nF
C155 "Capacitor" C0402 136.025,18.925 r270 top value=100nF
C156 "Capacitor" C0402 158.85,19.25 r0 top value=100pF
C157 "Capacitor" C0402 36.755,18.425 r0 top value=10nF
C158 "Capacitor" C0402 39.075,18.425 r0 top value=10nF
C159 "Capacitor" C0805 158.425,17.9 r0 top value=2.2uF
C160 "Capacitor" C0402 41.6,17.85 r90 top value=2.2uF
C161 "Capacitor" C1206_H1P6 129.045,15.715 r0 top value=220uF
C162 "Capacitor" C0402 151.045,13.3 r270 top value=22pF
C163 "Capacitor" C0402 129.795,13.626 r0 top value=100nF
C164 "Capacitor" C0402 38.25,13.15 r90 top value=100pF
C165 "Capacitor" C0603 29.975,12.625 r90 top value=10uF
C166 "Capacitor" C0402 35.6,12.875 r90 top value=100nF
C168 "Capacitor" C0402 165.075,9.125 r180 top value=470pF
C169 "Capacitor" C0603 29.52,7.525 r270 top value=10uF
C170 "Capacitor" C0603 162.8,7.045 r90 top value=100nF
C171 "Capacitor" C0402 161.65,6.85 r90 top value=470pF
C172 "Capacitor" C0402 34.475,6.15 r180 top value=100nF
C173 "Capacitor" C0402 34.475,4.075 r180 top value=10nF
C174 "Capacitor" C0402 55.275,128.725 r180 bottom value=100nF
C175 "Capacitor" C0402 104.116,104.216 r0 bottom value=100nF
C176 "Capacitor" C0402 28.425,8.175 r90 top value=10uF
C177 "Capacitor" C0402 110.8,92.025 r0 bottom value=100nF
C178 "Capacitor" C0402 113.275,90 r270 bottom value=2.2uF
C179 "Capacitor" C0402 115.225,88.475 r270 bottom value=100nF
C180 "Capacitor" C0402 108.85,88.475 r0 bottom value=2.2uF
C181 "Capacitor" C0402 106.7,86.35 r90 bottom value=2.2uF
C182 "Capacitor" C0402 107.825,86.35 r90 bottom value=100nF
C183 "Capacitor" C0603 142.575,79.25 r270 bottom value=10uF
C184 "Capacitor" C0402 140.925,79.475 r270 bottom value=100nF
C185 "Capacitor" C0402 139.475,79.475 r270 bottom value=100nF
C186 "Capacitor" C0402 137.575,79.475 r270 bottom value=100nF
C187 "Capacitor" C0402 135.675,79.475 r270 bottom value=100nF
C188 "Capacitor" C0603 133.125,79.125 r270 bottom value=10uF
C189 "Capacitor" C0402 103.17,79.846 r0 bottom value=100nF
C190 "Capacitor" C0201_MURATA_GRM033_H0P3 91.15,79.375 r180 bottom value=100nF
C191 "Capacitor" C0201_MURATA_GRM033_H0P3 86.9,79.175 r0 bottom value=100nF
C192 "Capacitor" C0201_MURATA_GRM033_H0P3 87.8,78.375 r90 bottom value=100nF
C193 "Capacitor" C0201_MURATA_GRM033_H0P3 91.6,77.975 r270 bottom value=100nF
C194 "Capacitor" C0201_MURATA_GRM033_H0P3 88.35,77.2 r0 bottom value=100nF
C195 "Capacitor" C0201_MURATA_GRM033_H0P3 93.201,76.675 r90 bottom value=100nF
C196 "Capacitor" C0201_MURATA_GRM033_H0P3 90.85,76.925 r0 bottom value=100nF
C197 "Capacitor" C0201_MURATA_GRM033_H0P3 89.2,76.4 r90 bottom value=100nF
C198 "Capacitor" C0402 141,76.25 r180 bottom value=100nF
C199 "Capacitor" C0201_MURATA_GRM033_H0P3 94.05,75.875 r0 bottom value=1uF
C200 "Capacitor" C0201_MURATA_GRM033_H0P3 96.075,75.6 r90 bottom value=1uF
C201 "Capacitor" C0201_MURATA_GRM033_H0P3 90.025,75.825 r0 bottom value=100nF
C202 "Capacitor" C0402 141.025,75.425 r180 bottom value=100nF
C203 "Capacitor" C0201_MURATA_GRM033_H0P3 93.75,75.25 r0 bottom value=1uF
C204 "Capacitor" C0201_MURATA_GRM033_H0P3 92.55,75.25 r0 bottom value=1uF
C205 "Capacitor" C0201_MURATA_GRM033_H0P3 90.5,74.775 r90 bottom value=100nF
C206 "Capacitor" C0201_MURATA_GRM033_H0P3 97.28,74.91 r0 bottom value=100nF
C207 "Capacitor" C0201_MURATA_GRM033_H0P3 91.2,74.525 r270 bottom value=1uF
C208 "Capacitor" C0201_MURATA_GRM033_H0P3 94.425,74.48 r180 bottom value=1uF
C209 "Capacitor" C0201_MURATA_GRM033_H0P3 96.175,74.475 r180 bottom value=1uF
C210 "Capacitor" C0201_MURATA_GRM033_H0P3 92.826,74.475 r180 bottom value=1uF
C211 "Capacitor" C0402 142.175,73.675 r180 bottom value=100nF
C212 "Capacitor" C0201_MURATA_GRM033_H0P3 89.925,73.775 r0 bottom value=100nF
C213 "Capacitor" C0201_MURATA_GRM033_H0P3 93.601,73.65 r180 bottom value=1uF
C214 "Capacitor" C0201_MURATA_GRM033_H0P3 91.825,73.65 r180 bottom value=1uF
C215 "Capacitor" C0201_MURATA_GRM033_H0P3 95.232,73.625 r0 bottom value=1uF
C216 "Capacitor" C0201_MURATA_GRM033_H0P3 96.356,73.524 r0 bottom value=1uF
C217 "Capacitor" C0201_MURATA_GRM033_H0P3 97.5,72.925 r90 bottom value=1uF
C218 "Capacitor" C0201_MURATA_GRM033_H0P3 96.349,72.875 r180 bottom value=1uF
C219 "Capacitor" C0201_MURATA_GRM033_H0P3 92.825,72.825 r0 bottom value=1uF
C220 "Capacitor" C0201_MURATA_GRM033_H0P3 94.4,72.775 r180 bottom value=1uF
C221 "Capacitor" C0201_MURATA_GRM033_H0P3 92.025,72 r270 bottom value=1uF
C222 "Capacitor" C0201_MURATA_GRM033_H0P3 94.4,72 r0 bottom value=1uF
C223 "Capacitor" C0201_MURATA_GRM033_H0P3 93.3,72 r180 bottom value=1uF
C224 "Capacitor" C0201_MURATA_GRM033_H0P3 96.301,71.974 r0 bottom value=1uF
C225 "Capacitor" C0201_H0P5 90,71.8 r0 bottom value=4.7uF
C226 "Capacitor" C0402 140.1,71.25 r180 bottom value=100nF
C227 "Capacitor" C0201_MURATA_GRM033_H0P3 96.375,71.275 r180 bottom value=1uF
C228 "Capacitor" C0201_MURATA_GRM033_H0P3 91.2,71.2 r0 bottom value=1uF
C229 "Capacitor" C0201_MURATA_GRM033_H0P3 96.075,70.43 r270 bottom value=1uF
C230 "Capacitor" C0201_MURATA_GRM033_H0P3 96.675,70.425 r270 bottom value=1uF
C231 "Capacitor" C0201_MURATA_GRM033_H0P3 92.675,70.48 r0 bottom value=1uF
C232 "Capacitor" C0201_MURATA_GRM033_H0P3 94.45,70.425 r180 bottom value=1uF
C233 "Capacitor" C0201_MURATA_GRM033_H0P3 91.2,70.388 r180 bottom value=1uF
C234 "Capacitor" C0201_MURATA_GRM033_H0P3 89.575,70.025 r270 bottom value=100nF
C235 "Capacitor" C0201_H0P5 88.6,70.125 r180 bottom value=2.2uF
C236 "Capacitor" C0603 116.398,69.798 r180 bottom value=10uF
C237 "Capacitor" C0201_MURATA_GRM033_H0P3 97.45,69.675 r270 bottom value=1uF
C238 "Capacitor" C0402 141.525,69.175 r270 bottom value=100nF
C239 "Capacitor" C0402 139.8,69.55 r180 bottom value=100nF
C240 "Capacitor" C0201_MURATA_GRM033_H0P3 92.8,69.6 r0 bottom value=1uF
C241 "Capacitor" C0201_MURATA_GRM033_H0P3 91.2,69.6 r180 bottom value=1uF
C242 "Capacitor" C0201_MURATA_GRM033_H0P3 94.475,69.575 r180 bottom value=1uF
C243 "Capacitor" C0201_MURATA_GRM033_H0P3 96.25,69.575 r180 bottom value=1uF
C244 "Capacitor" C0201_MURATA_GRM033_H0P3 87.65,69.425 r0 bottom value=100nF
C245 "Capacitor" C0402 122.975,68.7 r90 bottom value=100nF
C246 "Capacitor" C0201_MURATA_GRM033_H0P3 97.075,67.825 r0 bottom value=100nF
C247 "Capacitor" C0402 122.125,66.975 r0 bottom value=100nF
C248 "Capacitor" C0201_MURATA_GRM033_H0P3 88.375,66.125 r270 bottom value=100nF
C249 "Capacitor" C0201_MURATA_GRM033_H0P3 99.65,66.325 r180 bottom value=100nF
C250 "Capacitor" C0201_MURATA_GRM033_H0P3 87.025,65.875 r270 bottom value=1uF
C251 "Capacitor" C0201_MURATA_GRM033_H0P3 97.3,65.575 r270 bottom value=100nF
C252 "Capacitor" C0201_MURATA_GRM033_H0P3 99.775,65.675 r180 bottom value=100nF
C253 "Capacitor" C0201_MURATA_GRM033_H0P3 98.85,65.275 r90 bottom value=100nF
C254 "Capacitor" C0603 138.45,64.35 r90 bottom value=10uF
C255 "Capacitor" C0402 136.25,64.15 r90 bottom value=100nF
C256 "Capacitor" C0402 134.35,64.15 r90 bottom value=100nF
C257 "Capacitor" C0402 132.45,64.15 r90 bottom value=100nF
C258 "Capacitor" C0402 130.55,64.15 r90 bottom value=100nF
C259 "Capacitor" C0402 128.65,64.15 r90 bottom value=100nF
C260 "Capacitor" C0201_MURATA_GRM033_H0P3 99.775,64.675 r180 bottom value=100nF
C261 "Capacitor" C0402 126.75,62.9 r180 bottom value=100nF
C262 "Capacitor" C0402 122.15,61.75 r0 bottom value=100nF
C264 "Capacitor" C0402 106.7,59.525 r180 bottom value=100nF
C265 "Capacitor" C0201_H0P3 147.9,56.15 r270 bottom value=100nF
C266 "Capacitor" C0201_H0P3 147.9,54.85 r90 bottom value=100nF
C267 "Capacitor" C0201_H0P3 147.95,43.1 r90 bottom value=100nF
C268 "Capacitor" C0201_H0P3 139.75,38.7 r90 bottom value=100nF
C269 "Capacitor" C0201_H0P3 138.25,37.1 r90 bottom value=100nF
C270 "" C0402 92.925,36.15 r0 bottom value=100nF
C271 "" C0402 91.225,36.15 r180 bottom value=100nF
C272 "Capacitor" C0201_H0P3 147.9,34.55 r270 bottom value=100nF
C273 "Capacitor" C0402 128,34.025 r90 bottom value=100nF
C274 "Capacitor" C0201_H0P3 147.9,33.25 r90 bottom value=100nF
C275 "Capacitor" C0402 125.475,33 r180 bottom value=100nF
C276 "Capacitor" C0402 130.525,32 r0 bottom value=100nF
C277 "Capacitor" C0402 130.525,31.125 r0 bottom value=4.7uF
C278 "" C0603 109.325,29.6 r270 bottom value=22uF
C279 "" C0603 84.325,29.6 r90 bottom value=22uF
C280 "" C0603 59.325,29.6 r90 bottom value=22uF
C281 "Capacitor" C0402 39.35,29.475 r90 bottom value=100nF
C282 "Capacitor" C0402 38.05,29.475 r90 bottom value=100nF
C283 "Capacitor" C0402 130.525,29.5 r0 bottom value=100nF
C284 "Capacitor" C0402 125.475,29.5 r180 bottom value=100nF
C285 "Capacitor" C0402 128,28.975 r270 bottom value=100nF
C286 "" C0603 112.075,28.15 r90 bottom value=22uF
C287 "" C0603 87.075,28.15 r90 bottom value=22uF
C288 "" C0603 62.075,28.15 r90 bottom value=22uF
